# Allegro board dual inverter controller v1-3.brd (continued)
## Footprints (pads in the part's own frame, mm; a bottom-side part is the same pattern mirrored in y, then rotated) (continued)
OKI-78SR-H
  rect 1.499x1.499 hole 0.991: 1(0,2.54)
  round 1.499 hole 0.991: 2(0,0) 3(0,-2.54)
PHOENIX_1766877
  round 2.286 hole 1.397: 1(0,0) 2(0,-7.62) 3(0,-15.24) 4(0,-22.86) 5(0,-30.48) 6(0,-38.1) 7(0,-45.72) 8(0,-53.34) 9(0,-60.96) 10(0,-68.58) 11(0,-76.2) 12(0,-83.82)
POWER-SO8
  rect 0.63x0.65 smd: 1(-2.735,1.905) 2(-2.735,0.635) 3(-2.735,-0.635) 4(-2.735,-1.905) 5(2.735,-1.905) 6(2.735,-0.635) 7(2.735,0.635) 8(2.735,1.905)
RESC1608X55N
  rect 0.9x1 smd: 1(-0.8,0) 2(0.8,0)
RESC1608X65N
  rect 0.9x1 smd: 1(-0.8,0) 2(0.8,0)
RESC2012X60N
  rect 0.95x1.4 smd: 1(-1,0) 2(1,0)
RESC2012X70N
  rect 1.05x1.4 smd: 1(-0.95,0) 2(0.95,0)
RESC3216X65N
  rect 1.15x1.8 smd: 1(-1.45,0) 2(1.45,0)
RESC6432X70N
  rect 1.25x3.4 smd: 1(-3.05,0) 2(3.05,0)
RJ45_VERT_SHIELD_CON
  round 4.064 hole 3.556: (-10.16,6.35) (1.27,6.35)
  round 1.524 hole 1.016: 1(0,0) 2(-1.27,-2.54) 3(-2.54,0) 4(-3.81,-2.54) 5(-5.08,0) 6(-6.35,-2.54) 7(-7.62,0) 8(-8.89,-2.54)
  round 2.54 hole 1.702: S1(3.353,9.398) S2(-12.243,9.398)
RW-20_ADI
  rect 1.676x0.508 smd: 1(-4.636,5.715) 2(-4.636,4.445) 3(-4.636,3.175) 4(-4.636,1.905) 5(-4.636,0.635) 6(-4.636,-0.635) 7(-4.636,-1.905) 8(-4.636,-3.175) 9(-4.636,-4.445) 10(-4.636,-5.715) 11(4.636,-5.715) 12(4.636,-4.445) 13(4.636,-3.175) 14(4.636,-1.905) 15(4.636,-0.635) 16(4.636,0.635) 17(4.636,1.905) 18(4.636,3.175) 19(4.636,4.445) 20(4.636,5.715)
SOD-123F-AC
  rect 0.914x1.27 smd: 1(1.651,0) 2(-1.651,0)
SOD-323-AC
  rect 0.635x0.838 smd: A(-1.118,0) C(1.27,0)
SOP65P640X120-20AN
  rect 1.5x0.45 smd: 1(-2.95,2.925) 2(-2.95,2.275) 3(-2.95,1.625) 4(-2.95,0.975) 5(-2.95,0.325) 6(-2.95,-0.325) 7(-2.95,-0.975) 8(-2.95,-1.625) 9(-2.95,-2.275) 10(-2.95,-2.925) 11(2.95,-2.925) 12(2.95,-2.275) 13(2.95,-1.625) 14(2.95,-0.975) 15(2.95,-0.325) 16(2.95,0.325) 17(2.95,0.975) 18(2.95,1.625) 19(2.95,2.275) 20(2.95,2.925)
SOP65P640X120-24N
  rect 1.45x0.45 smd: 1(-2.95,3.575) 2(-2.95,2.925) 3(-2.95,2.275) 4(-2.95,1.625) 5(-2.95,0.975) 6(-2.95,0.325) 7(-2.95,-0.325) 8(-2.95,-0.975) 9(-2.95,-1.625) 10(-2.95,-2.275) 11(-2.95,-2.925) 12(-2.95,-3.575) 13(2.95,-3.575) 14(2.95,-2.925) 15(2.95,-2.275) 16(2.95,-1.625) 17(2.95,-0.975) 18(2.95,-0.325) 19(2.95,0.325) 20(2.95,0.975) 21(2.95,1.625) 22(2.95,2.275) 23(2.95,2.925) 24(2.95,3.575)
SOT23-5_0_95X2_70P_H1_22
  rect 1.05x0.6 smd: 1(-1.35,0.95) 2(-1.35,0) 3(-1.35,-0.95) 4(1.35,-0.95) 5(1.35,0.95)
SOT23-5_0_95X2_70P_H1_45
  rect 1.05x0.6 smd: 1(-1.35,0.95) 2(-1.35,0) 3(-1.35,-0.95) 4(1.35,-0.95) 5(1.35,0.95)
SOT363_NEX
  rect 0.787x0.356 smd: 1(-1.067,0.65) 2(-1.067,0) 3(-1.067,-0.65) 4(1.067,-0.65) 5(1.067,0) 6(1.067,0.65)
SOT-23-3-D
  rect 0.787x0.889 smd: 1(3.327,2.87) 2(1.448,2.87) 3(2.388,0.864)
SOT_23_3
  rect 0.787x0.889 smd: 1(3.327,2.87) 2(1.448,2.87) 3(2.388,0.864)
SOT_23_6
  rect 0.61x1.067 smd: 1(0,0) 2(0.953,0) 3(1.905,0) 4(1.905,2.692) 5(0.953,2.692) 6(0,2.692)
TSSOP-14
  rect 1.651x0.406 smd: 1(0,0) 2(0,-0.66) 3(0,-1.321) 4(0,-1.981) 5(0,-2.642) 6(0,-3.302) 7(0,-3.962) 8(6.096,-3.962) 9(6.096,-3.302) 10(6.096,-2.642) 11(6.096,-1.981) 12(6.096,-1.321) 13(6.096,-0.66) 14(6.096,0)
TSSOP-16P_P65MM
  oval 1.6x0.45 smd: 1(-2.85,2.275) 2(-2.85,1.625) 3(-2.85,0.975) 4(-2.85,0.325) 5(-2.85,-0.325) 6(-2.85,-0.975) 7(-2.85,-1.625) 8(-2.85,-2.275) 9(2.85,-2.275) 10(2.85,-1.625) 11(2.85,-0.975) 12(2.85,-0.325) 13(2.85,0.325) 14(2.85,0.975) 15(2.85,1.625) 16(2.85,2.275)
unnamed#2
  round 0.025 hole 3.277 unplated: (0,0)
VFSOP-8
  rect 0.762x0.254 smd: 1(-1.549,0.762) 2(-1.549,0.254) 3(-1.549,-0.254) 4(-1.549,-0.762) 5(1.549,-0.762) 6(1.549,-0.254) 7(1.549,0.254) 8(1.549,0.762)

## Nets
+1V5REF: CT58.1 RT61.1 RT73.1 RT90.1 RT112.1 RT136.1 RT173.1 UT16.1(VREF/2)
+1V5REF_RSLV: CB46.1 CT48.1 CT49.1 CT56.1 CT57.1 CT66.1 CT67.1 CT74.1 CT75.1 RT91.2 RT100.2 RT113.2 RT122.2 UB16.1(VREF/2)
+3V3: CB5.1 CB8.1 CB12.1 CB13.1 CB14.1 CB21.1 CB22.1 CB23.1 CB27.1 CB28.1 CB29.1 CB36.1 CB37.1 CB38.1 CB39.1 CB43.1 CB54.1 CB68.1 CB70.1 CB72.1 CT2.1 CT7.1 CT16.1 CT21.1 CT31.1 CT33.1 CT36.1 CT42.1 CT43.1 CT51.1 CT52.1 CT60.1 CT62.1 CT69.1 CT70.1 CT89.1 CT108.1 CT119.1 CT125.1 CT126.1 CT130.1 CT145.1 CT156.1 CT160.1 CT163.1 JT2.7 JT17.5 RB2.1 RB3.1 RB6.1 RB13.1 RB27.2 RB29.1 RB30.1 RB31.1 RB47.1 RB48.1 RB49.1 RB91.1 RB95.1 RB110.1 RB111.1 RB113.1 RB118.1 RT53.2 RT54.2 RT78.1 RT192.1 RT229.2 RT238.2 UB1.3 UB1.4 UB2.5 UB3.3 UB3.8(VCC) UB4.3 UB4.8(VCC) UB5.3 UB5.8(VCC) UB6.5 UB7.5 UB8.5 UB9.3 UB9.8(VCC) UB10.3 UB10.8(VCC) UB11.3 UB11.8(VCC) UB12.5 UB13.5 UB14.5 UB15.5 UB16.3 UB16.4 UB17.5 UB20.5 UB21.3 UB21.4 UB22.1 UT1.16 UT2.16 UT3.5 UT4.16 UT8.16 UT10.5 UT11.5 UT13.5 UT14.5 UT15.5 UT16.3 UT16.4 UT17.5 UT18.5 UT19.5 UT21.5 UT25.16 UT26.16 UT32.5 UT33.3(OUTPUT) UT34.16 UT35.16 UT38.4 UT39.5 UT40.5
+3VREF_A: CB4.1 RB15.1 RB16.1 RB17.1 UB1.5
+3VREF_B: CB71.1 RB92.1 RB93.1 RB94.1 UB21.5
+5V: CB44.1 CB45.1 CB73.1 CT22.1 CT23.1 CT24.1 CT121.1 CT122.1 CT123.1 CT128.1 CT129.1 CT146.1 CT150.1 CT153.1 JB1.2 JB5.2 JT26.48 JT26.84 JT26.98 JT26.112 JT26.158 JT26.180 JT41.4 JT41.9(PIN9) RT148.1 RT156.1 RT166.1 RT172.1 RT186.1 RT193.1 RT194.1 UB18.20 UB19.20 UB22.23(VCCB1) UB22.24 UT5.4 UT6.4 UT7.4 UT27.20 UT28.20 UT29.4 UT30.4 UT31.4 UT36.3(OUTPUT) UT38.3
+5V-ISO: CT151.1 CT154.1 CT155.1 JT3.9 LT26.2 UT38.16
+12V: CT90.1 CT111.1 CT134.1 CT147.1 DT2.A JB2.1 JB3.1 JB4.1 JB6.1 JB7.1 JB8.1 JT2.1 LT13.1 RT145.1 RT146.2 RT220.2 UT22.5 UT33.1 UT36.1 UT37.8(VOUT)
+15V: CT87.1 CT95.1 CT161.1 DT10.2 DT10.5 DT11.2 DT11.5 DT12.2 DT12.5 DT13.2 DT13.5 DT14.2 DT14.5 DT15.2 DT15.5 QT1.5 QT1.6 QT1.7 QT1.8 RB114.1 RB117.1 RT235.1 RT239.1 UT41.10(VS_O(2)) UT41.11 UT41.12 UT43.10(VS_O(2)) UT43.11 UT43.12
VIN: JT42.1 QT3.5 QT3.6 QT3.7 QT3.8 RT217.1 RT223.1 UT37.1
0: CB1.1 CB2.1 CB3.1 CB4.2 CB5.2 CB6.2 CB8.2 CB9.1 CB10.1 CB11.2 CB12.2 CB13.2 CB14.2 CB18.1 CB19.1 CB20.1 CB21.2 CB22.2 CB23.2 CB27.2 CB28.2 CB29.2 CB33.1 CB34.1 CB35.1 CB36.2 CB37.2 CB38.2 CB39.2 CB43.2 CB44.2 CB45.2 CB46.2 CB47.2 CB48.2 CB49.2 CB50.2 CB51.2 CB52.2 CB53.2 CB54.2 CB55.2 CB56.2 CB57.2 CB58.2 CB59.2 CB60.2 CB61.2 CB62.2 CB63.2 CB64.2 CB65.2 CB66.2 CB67.2 CB68.2 CB69.2 CB70.2 CB71.2 CB72.2 CB73.2 CB74.1 CB75.1 CB76.1 CB79.2 CB81.2 CB83.2 CB84.2 CT1.2 CT2.2 CT3.2 CT4.2 CT5.2 CT6.2 CT7.2 CT8.2 CT9.1 CT10.2 CT11.1 CT12.2 CT13.1 CT14.2 CT15.1 CT16.2 CT21.2 CT22.2 CT23.2 CT24.2 CT31.2 CT33.2 CT34.1 CT36.2 CT37.2 CT39.1 CT40.2 CT42.2 CT43.2 CT45.2 CT47.1 CT48.2 CT51.2 CT52.2 CT54.2 CT56.2 CT58.2 CT59.2 CT60.2 CT62.2 CT63.2 CT65.1 CT66.2 CT69.2 CT70.2 CT72.2 CT74.2 CT81.1 CT87.2 CT88.2 CT89.2 CT90.2 CT91.2 CT95.2 CT97.1 CT98.1 CT99.2 CT100.2 CT103.1 CT104.2 CT106.2 CT107.2 CT108.2 CT109.2 CT110.2 CT111.2 CT112.1 CT116.2 CT118.2 CT119.2 CT120.2 CT121.2 CT122.2 CT123.2 CT124.2 CT125.2 CT126.2 CT127.2 CT128.2 CT129.2 CT130.2 CT131.2 CT134.2 CT136.1 CT137.2 CT138.1 CT139.2 CT140.1 CT141.2 CT145.2 CT146.2 CT147.2 CT148.2 CT149.2 CT150.2 CT153.2 CT156.2 CT160.2 CT161.2 CT163.2 CT164.1 DT4.2(C) DT5.2(C) DT6.2(C) DT7.2(C) DT8.2(C) DT10.1 DT10.4(C2) DT11.1 DT11.4(C2) DT12.1 DT12.4(C2) DT13.1 DT13.4(C2) DT14.1 DT14.4(C2) DT15.1 DT15.4(C2) JB1.1 JB1.S1 JB1.S2(SHIELD2) JB2.2 JB2.12 JB2.14 JB2.16 JB3.2 JB3.12 JB3.14 JB3.16 JB4.2 JB4.12 JB4.14 JB4.16 JB5.1 JB5.S1 JB5.S2(SHIELD2) JB6.2 JB6.12 JB6.14 JB6.16 JB7.2 JB7.12 JB7.14 JB7.16 JB8.2 JB8.12 JB8.14 JB8.16 JT2.2 JT2.8 JT4.2 JT4.3 JT4.4 JT4.5 JT5.2 JT5.3 JT5.4 JT5.5 JT6.2 JT6.3 JT6.4 JT6.5 JT7.2 JT7.3 JT7.4 JT7.5 JT8.2 JT8.3 JT8.4 JT8.5 JT9.2 JT9.3 JT9.4 JT9.5 JT10.2 JT10.3 JT10.4 JT10.5 JT11.2 JT11.3 JT11.4 JT11.5 JT12.2 JT12.3 JT12.4 JT12.5 JT13.2 JT13.3 JT13.4 JT13.5 JT14.2 JT14.3 JT14.4 JT14.5 JT15.2 JT16.2 JT16.3 JT16.4 JT16.5 JT17.4 JT17.8 JT17.10 JT17.12 JT19.2 JT19.3 JT19.4 JT19.5 JT20.2 JT20.3 JT20.4 JT20.5 JT21.2 JT21.3 JT21.4 JT21.5 JT23.2 JT23.3 JT23.4 JT23.5 JT24.2 JT24.3 JT24.4 JT24.5 JT25.2 JT25.3 JT25.4 JT25.5 JT26.7 JT26.10 JT26.13 JT26.16 JT26.19 JT26.22 JT26.29 JT26.35 JT26.38 JT26.46 JT26.47 JT26.65 JT26.83 JT26.97 JT26.111 JT26.135 JT26.157 JT26.179 JT26.G1 JT26.G2 JT26.G3 JT26.G4 JT27.2 JT27.3 JT27.4 JT27.5 JT28.2 JT28.3 JT28.4 JT28.5 JT29.2 JT29.3 JT29.4 JT29.5 JT30.2 JT30.3 JT30.4 JT30.5 JT31.2 JT31.3 JT31.4 JT31.5 JT32.2 JT32.3 JT32.4 JT32.5 JT33.2 JT33.3 JT33.4 JT33.5 JT34.2 JT34.3 JT34.4 JT34.5 JT35.2 JT35.3 JT35.4 JT35.5 JT36.2 JT36.3 JT36.4 JT36.5 JT37.2 JT37.3 JT37.4 JT37.5 JT38.2 JT38.3 JT38.4 JT38.5 JT39.2 JT39.3 JT39.4 JT39.5 JT40.2 JT40.3 JT40.4 JT40.5 JT41.5 JT41.10 JT42.2 JT42.3 RB1.1 RB4.1 RB5.2 RB7.2 RB9.2 RB11.2 RB14.2 RB28.1 RB90.1 RB96.1 RB98.2 RB100.2 RB102.2 RB109.2 RB112.2 RB115.2 RB116.2 RB119.2 RB120.2 RT27.1 RT144.1 RT147.2 RT160.2 RT221.2 RT225.2 RT226.2 RT227.2 RT234.2 RT245.2 UB1.2 UB2.2(V-) UB3.1 UB3.4 UB4.1 UB4.4 UB5.1 UB5.4 UB6.2(V-) UB7.2(V-) UB8.2(V-) UB9.1 UB9.4 UB10.1 UB10.4 UB11.1 UB11.4 UB12.2(V-) UB13.2(V-) UB14.2(V-) UB15.2 UB16.2 UB17.2 UB18.1 UB18.2 UB18.3 UB18.10 UB18.19 UB19.1 UB19.5 UB19.6 UB19.7 UB19.8 UB19.9 UB19.10 UB19.19 UB20.2 UB21.2 UB22.2 UB22.11 UB22.12 UB22.13 UB22.14 UB22.15 UB22.22 UT1.8 UT2.8 UT3.2(V-) UT4.8 UT5.2 UT5.3 UT5.11 UT6.2 UT6.3 UT6.11 UT7.2 UT7.3 UT7.11 UT8.8 UT10.2(V-) UT11.2(V-) UT13.2(V-) UT14.2(V-) UT15.2(V-) UT16.2 UT17.2(V-) UT18.2(V-) UT19.2(V-) UT21.2(V-) UT22.16 UT22.17 UT24.2(S) UT25.8 UT26.8 UT27.1 UT27.2 UT27.3 UT27.10 UT27.19 UT28.1 UT28.5 UT28.6 UT28.7 UT28.8 UT28.9 UT28.10 UT28.19 UT29.2 UT29.3 UT29.11 UT30.2 UT30.3 UT30.11 UT31.2 UT31.3 UT31.11 UT32.2(V-) UT33.2 UT34.8 UT35.8 UT36.2 UT37.5 UT38.1 UT38.2 UT38.10 UT39.2(V-) UT40.2(V-) UT41.6 UT41.14 UT41.EPAD UT43.6 UT43.14 UT43.EPAD
1: CT151.2 CT154.2 CT155.2 DT9.3(A3) JT3.3 JT3.5 JT3.10 JT3.11(SHIELD1) LT27.2 RT228.2 UT38.11 UT38.15
CANA-H: DT9.1 JT3.7 RT224.1 UT38.14
CANA-L: DT9.2 JT3.2 RT224.2 UT38.13
CANA-RX: JT26.80 UT38.5
CANA-TX: JT26.82 UT38.7
CASE-TEMP: CB11.1 JT26.30 RB26.2
COS-A: CT54.1 JT20.1(SIGNAL) JT26.36 RT99.2
COS-A-N: CT53.1 DT13.3 JT18.6 RT95.1 RT96.1
COS-A-P: CT53.2 DT13.6 JT18.5 RT93.1 RT95.2
COS-B: CT72.1 JT26.42 JT27.1(SIGNAL) RT121.2
COS-B-N: CT71.1 DT10.3 JT22.6 RT117.1 RT119.1
COS-B-P: CT71.2 DT10.6 JT22.5 RT115.1 RT117.2
CURRENT-U: CB55.1 JT11.1(SIGNAL) JT26.12 RT50.2
CURRENT-U_N: JB1.3 RT4.2 RT14.1
CURRENT-U_P: JB1.6 RT4.1 RT15.1
CURRENT-V: CB56.1 JT4.1(SIGNAL) JT26.14 RT51.2
CURRENT-V_N: JB1.5 RT5.2 RT16.1
CURRENT-V_P: JB1.4 RT5.1 RT17.1
CURRENT-W: CB57.1 JT12.1(SIGNAL) JT26.18 RT52.2
CURRENT-W_N: JB1.7 RT6.2 RT18.1
CURRENT-W_P: JB1.8 RT6.1 RT19.1
CURRENT-X: CB60.1 JT26.26 JT40.1(SIGNAL) RT171.2
CURRENT-X_N: JB5.7 RT210.1 RT213.2
CURRENT-X_P: JB5.8 RT209.1 RT213.1
CURRENT-Y: CB59.1 JT26.24 JT39.1(SIGNAL) RT170.2
CURRENT-Y_N: JB5.5 RT208.1 RT212.2
CURRENT-Y_P: JB5.4 RT207.1 RT212.1
CURRENT-Z: CB58.1 JT26.20 JT38.1(SIGNAL) RT169.2
CURRENT-Z_N: JB5.3 RT206.1 RT211.2
CURRENT-Z_P: JB5.6 RT205.1 RT211.1
EMUI: JT17.14 JT26.1
EMUO: JT17.13 JT26.2
EXC-A-N: CT158.2 DT15.3 JT18.2 RT233.2 UT41.9
EXC-A-P: CT157.2 DT15.6 JT18.1 RT230.2 UT41.13
EXC-B-N: CT166.2 DT12.3 JT22.2 RT244.2 UT43.9
EXC-B-P: CT162.2 DT12.6 JT22.1 RT237.2 UT43.13
GLOBAL-FAULT-ALL: JT16.1(SIGNAL) JT26.134 UB17.4(Y)
GLOBAL-FAULT-UVW: JT26.130 UB15.4(Y) UB17.3
GLOBAL-FAULT-XYZ: JT26.132 UB17.6 UB20.4(Y)
I2CA-SCL: JT2.9 JT26.87 RT54.1
I2CA-SDA: JT2.10 JT26.85 RT53.1
LED-G: JT26.133 RT154.1
LED-R: JT26.129 RT152.1
LED-Y: JT26.131 RT153.1
PWM7A: JT2.12 JT26.58
PWM7B: JT2.11 JT26.60
PWM8A: JT2.14 JT26.62
PWM8B: JT2.13 JT26.64
PWM9A: JT26.167 RT66.1
PWM9B: JT26.168 RT75.1
QEA_A: JT26.68 UB22.3
QEA_B: JT26.70 UB22.4
QEA_I: JT26.74 UB22.5
QEB_A: JT26.100 UB22.6
QEB_B: JT26.102 UB22.7
QEB_I: JT26.106 UB22.8
QEPA-A-IN: CT118.1 JT41.1 RT186.2 UB22.21
QEPA-B-IN: CT131.1 JT41.2 RT194.2 UB22.20
QEPA-I-IN: CT116.1 JT41.3 RT172.2 UB22.19
QEPB-A-IN: CT106.1 JT41.6 RT166.2 UB22.18
QEPB-B-IN: CT99.1 JT41.7 RT156.2 UB22.17
QEPB-I-IN: CT91.1 JT41.8 RT148.2 UB22.16
RSLV-A-PWM: JT26.169 RT163.1
RSLV-B-PWM: JT26.170 RT242.1
SD-C1: JT2.15 JT26.101
SD-C2: JT2.17 JT26.105
SD-C3: JT2.19 JT26.109
SD-D1: JT2.16 JT26.99
SD-D2: JT2.18 JT26.103
SD-D3: JT2.20 JT26.107
SHUTDOWN+15V: JT26.155 RT160.1 RT161.1
SIN-A: CT45.1 JT19.1(SIGNAL) JT26.34 RT83.2
SIN-A-N: CT44.1 DT14.3 JT18.4 RT80.1 RT81.1
SIN-A-P: CT44.2 DT14.6 JT18.3 RT79.1 RT80.2
SIN-B: CT63.1 JT23.1(SIGNAL) JT26.40 RT105.2
SIN-B-N: CT61.1 DT11.3 JT22.4 RT102.1 RT103.1
SIN-B-P: CT61.2 DT11.6 JT22.3 RT101.1 RT102.2
SPIA-CLK: JT2.6 JT26.71
SPIA-MISO: JT2.5 JT26.69
SPIA-MOSI: JT2.3 JT26.67
SPIA-STE: JT2.4 JT26.73
TCK: JT17.9 JT17.11 JT26.5
TDI: JT17.3 JT26.8
TDO: JT17.7 JT26.6
TMS: JT17.1 JT26.3
TRST: JT17.2 JT26.4
U-FAULT: JT26.122 UB15.1 UT8.3
U-FAULT-N: JB4.8 LT12.1
U-FAULT-N-FILTER: CT27.2 LT12.2 RT49.2 UT8.1
U-FAULT-P: JB4.7 LT9.1
U-FAULT-P-FILTER: CT27.1 LT9.2 RT49.1 UT8.2
U-LEN: JB4.13 UB18.12
U-LEN-OUT: JT26.144 UB18.8
U-OCEN: JB4.15 UB18.11(Y8)
U-OCEN-OUT: JT26.142 UB18.9
U-PSDIS: JB4.11 UB18.13
U-PSDIS-OUT: JT26.146 UB18.7
U-RTD: JT26.92 RB32.1 UB3.2 UT8.5
U-RTD-N: JB4.10 LT3.1
U-RTD-N-FILTER: CT20.2 LT3.2 RT32.2 UT8.7
U-RTD-P: JB4.9 LT6.1
U-RTD-P-FILTER: CT20.1 LT6.2 RT32.1 UT8.6
U-TEMP: CB48.1 JT26.25 RB66.2
UHS-PWM: JT9.1(SIGNAL) JT26.49 RT20.1
UHS-PWM-N: JB4.4 UT1.3
UHS-PWM-P: JB4.3 UT1.2
ULS-PWM: JT10.1(SIGNAL) JT26.51 RT3.1
ULS-PWM-N: JB4.6 UT1.5
ULS-PWM-P: JB4.5 UT1.6
V-FAULT: JT26.124 UB15.3 UT8.11
V-FAULT-N: JB3.8 LT1.1
V-FAULT-N-FILTER: CT18.2 LT1.2 RT30.2 UT8.9
V-FAULT-P: JB3.7 LT4.1
V-FAULT-P-FILTER: CT18.1 LT4.2 RT30.1 UT8.10
V-LEN: JB3.13 UB18.15
V-LEN-OUT: JT26.152 UB18.5
V-OCEN: JB3.15 UB18.14
V-OCEN-OUT: JT26.150 UB18.6
V-PSDIS: JB3.11 UB18.16
V-PSDIS-OUT: JT26.154 UB18.4
V-RTD: JT26.94 RB33.1 UB4.2 UT8.13(Y4)
V-RTD-N: JB3.10 LT11.1
V-RTD-N-FILTER: CT26.2 LT11.2 RT48.2 UT8.15
V-RTD-P: JB3.9 LT8.1
V-RTD-P-FILTER: CT26.1 LT8.2 RT48.1 UT8.14
V-TEMP: CB49.1 JT26.27 RB67.2
V_U+: JT43.12 RT55.1
V_U-: JT43.11 RB19.1
V_V+: JT43.10 RT67.1
V_V-: JT43.9 RB41.1
V_W+: JT43.8 RT84.1
V_W-: JT43.7 RB59.1
V_X+: JT43.6 RT106.1
V_X-: JT43.5 RB74.1
V_Y+: JT43.4 RT130.1
V_Y-: JT43.3 RB83.1
V_Z+: JT43.2 RT174.1
V_Z-: JT43.1 RB103.1
VDC-M: JT1.2 RT37.1
VDC-P: JT1.1 RT7.1
VHS-PWM: JT7.1(SIGNAL) JT26.53 RT2.1
VHS-PWM-N: JB3.4 UT1.11
VHS-PWM-P: JB3.3 UT1.10
VLS-PWM: JT8.1(SIGNAL) JT26.55 RT13.1
VLS-PWM-N: JB3.6 UT1.13(Z4)
VLS-PWM-P: JB3.5 UT1.14
VSENSE-DC: CB61.1 JT21.1(SIGNAL) JT26.28 RB65.2
VSENSE-U: CB62.1 JT24.1(SIGNAL) JT26.9 RB72.2
VSENSE-V: CB63.1 JT25.1(SIGNAL) JT26.11 RB73.2
VSENSE-W: CB64.1 JT26.15 JT28.1(SIGNAL) RB80.2
VSENSE-X: CB65.1 JT26.17 JT29.1(SIGNAL) RB81.2
VSENSE-Y: CB66.1 JT26.21 JT30.1(SIGNAL) RB82.2
VSENSE-Z: CB67.1 JT26.23 JT31.1(SIGNAL) RB89.2
W-FAULT: JT26.126 UB15.6 UT4.3
W-FAULT-N: JB2.8 LT2.1
W-FAULT-N-FILTER: CT19.2 LT2.2 RT31.2 UT4.1
W-FAULT-P: JB2.7 LT5.1
W-FAULT-P-FILTER: CT19.1 LT5.2 RT31.1 UT4.2
W-LEN: JB2.13 UB19.17
W-LEN-OUT: JT26.162 UB19.3
W-OCEN: JB2.15 UB19.16
W-OCEN-OUT: JT26.160 UB19.4
W-PSDIS: JB2.11 UB19.18
W-PSDIS-OUT: JT26.164 UB19.2
W-RTD: JT26.96 RB34.1 UB5.2 UT4.5
W-RTD-N: JB2.10 LT10.1
W-RTD-N-FILTER: CT25.2 LT10.2 RT47.2 UT4.7
W-RTD-P: JB2.9 LT7.1
W-RTD-P-FILTER: CT25.1 LT7.2 RT47.1 UT4.6
W-TEMP: CB50.1 JT26.31 RB68.2
WHS-PWM: JT5.1(SIGNAL) JT26.50 RT1.1
WHS-PWM-N: JB2.4 UT2.3
WHS-PWM-P: JB2.3 UT2.2
WLS-PWM: JT6.1(SIGNAL) JT26.52 RT28.1
WLS-PWM-N: JB2.6 UT2.5
WLS-PWM-P: JB2.5 UT2.6
X-FAULT: JT26.121 UB20.1 UT35.3
X-FAULT-N: JB8.8 LT25.1
X-FAULT-N-FILTER: CT144.2 LT25.2 RT216.2 UT35.1
X-FAULT-P: JB8.7 LT22.1
X-FAULT-P-FILTER: CT144.1 LT22.2 RT216.1 UT35.2
X-LEN: JB8.13 UT27.12
X-LEN-OUT: JT26.143 UT27.8
X-OCEN: JB8.15 UT27.11(Y8)
X-OCEN-OUT: JT26.141 UT27.9
X-PSDIS: JB8.11 UT27.13
X-PSDIS-OUT: JT26.145 UT27.7
X-RTD: JT26.89 RB50.1 UB9.2 UT35.5
X-RTD-N: JB8.10 LT16.1
X-RTD-N-FILTER: CT135.2 LT16.2 RT204.2 UT35.7
X-RTD-P: JB8.9 LT19.1
X-RTD-P-FILTER: CT135.1 LT19.2 RT204.1 UT35.6
X-TEMP: CB51.1 JT26.33 RB69.2
XHS-PWM: JT26.54 JT36.1(SIGNAL) RT190.1
XHS-PWM-N: JB8.4 UT25.3
XHS-PWM-P: JB8.3 UT25.2
XLS-PWM: JT26.56 JT37.1(SIGNAL) RT168.1
XLS-PWM-N: JB8.6 UT25.5
XLS-PWM-P: JB8.5 UT25.6
Y-FAULT: JT26.123 UB20.3 UT35.11
Y-FAULT-N: JB7.8 LT14.1
Y-FAULT-N-FILTER: CT132.2 LT14.2 RT196.2 UT35.9
Y-FAULT-P: JB7.7 LT17.1
Y-FAULT-P-FILTER: CT132.1 LT17.2 RT196.1 UT35.10
Y-LEN: JB7.13 UT27.15
Y-LEN-OUT: JT26.151 UT27.5
Y-OCEN: JB7.15 UT27.14
Y-OCEN-OUT: JT26.149 UT27.6
Y-PSDIS: JB7.11 UT27.16
Y-PSDIS-OUT: JT26.153 UT27.4
Y-RTD: JT26.91 RB51.1 UB10.2 UT35.13(Y4)
Y-RTD-N: JB7.10 LT24.1
Y-RTD-N-FILTER: CT143.2 LT24.2 RT215.2 UT35.15
Y-RTD-P: JB7.9 LT21.1
Y-RTD-P-FILTER: CT143.1 LT21.2 RT215.1 UT35.14
Y-TEMP: CB52.1 JT26.37 RB70.2
YHS-PWM: JT26.57 JT34.1(SIGNAL) RT167.1
YHS-PWM-N: JB7.4 UT25.11
YHS-PWM-P: JB7.3 UT25.10
YLS-PWM: JT26.59 JT35.1(SIGNAL) RT185.1
YLS-PWM-N: JB7.6 UT25.13(Z4)
YLS-PWM-P: JB7.5 UT25.14
Z-FAULT: JT26.125 UB20.6 UT34.3
Z-FAULT-N: JB6.8 LT15.1
Z-FAULT-N-FILTER: CT133.2 LT15.2 RT197.2 UT34.1
Z-FAULT-P: JB6.7 LT18.1
Z-FAULT-P-FILTER: CT133.1 LT18.2 RT197.1 UT34.2
Z-LEN: JB6.13 UT28.17
Z-LEN-OUT: JT26.161 UT28.3
Z-OCEN: JB6.15 UT28.16
Z-OCEN-OUT: JT26.159 UT28.4
Z-PSDIS: JB6.11 UT28.18
Z-PSDIS-OUT: JT26.163 UT28.2
Z-RTD: JT26.93 RB52.1 UB11.2 UT34.5
Z-RTD-N: JB6.10 LT23.1
Z-RTD-N-FILTER: CT142.2 LT23.2 RT214.2 UT34.7
Z-RTD-P: JB6.9 LT20.1
Z-RTD-P-FILTER: CT142.1 LT20.2 RT214.1 UT34.6
Z-TEMP: CB53.1 JT26.39 RB71.2
ZHS-PWM: JT26.61 JT32.1(SIGNAL) RT165.1
ZHS-PWM-N: JB6.4 UT26.3
ZHS-PWM-P: JB6.3 UT26.2
ZLS-PWM: JT26.63 JT33.1(SIGNAL) RT195.1
ZLS-PWM-N: JB6.6 UT26.5
ZLS-PWM-P: JB6.5 UT26.6
N07282: RB13.2 UT8.4
N07299: RB5.1 UT8.12
N07508: RB6.2 UT4.4
N07516: RB14.1 UT4.12
N07693: RB3.2 UT1.4
N07878: RB2.2 UT2.4
N09835: CT6.1 RT20.2 UT1.1
N10049: CT4.1 RT3.2 UT1.7
N10085: CT3.1 RT2.2 UT1.9
N10121: CT5.1 RT13.2 UT1.15
N11382: RB1.2 UT1.12
N11987: RB4.2 UT2.12
N12714: CT1.1 RT1.2 UT2.1
N12754: CT14.1 RT28.2 UT2.7
N16187: CB24.2 RB66.1 UB6.1 UB6.4
N16636: CB24.1 RB35.2 RB38.1
N16643: CB18.2 RB38.2 UB6.3
N18013: CB25.1 RB36.2 RB39.1
N18021: CB25.2 RB67.1 UB7.1 UB7.4
N18093: CB19.2 RB39.2 UB7.3
N18488: CB26.1 RB37.2 RB40.1
N18496: CB26.2 RB68.1 UB8.1 UB8.4
N18568: CB20.2 RB40.2 UB8.3
N76078: CT15.2 RT12.2 RT27.2 RT29.1
N76134: RT29.2 UT3.3
N76224: CT17.2 RB65.1 RT36.2 UT3.1
N76236: RT43.2 UT3.4
N76260: CT17.1 RT36.1 RT42.2 RT43.1
N78650: CB7.1 RB18.1 RB25.2
N78658: CB7.2 RB26.1 UB2.1 UB2.4
N78724: CB9.2 RB18.2 UB2.3
N79088: CB10.2 RB25.1 RB27.1 RB28.2
N88263: DT7.1 RT192.2
N88433: DT8.1 RT193.2
N93191: DT4.1 RT152.2
N93195: DT6.1 RT154.2
N93199: DT5.1 RT153.2
N139937: RT10.2 RT11.1
N139941: RT11.2 RT12.1
N140053: RT40.2 RT41.1
N140057: RT41.2 RT42.1
N147166: QT2.1 QT2.2 QT2.3(S2) QT3.1 QT3.2 QT3.3(S2)
N148075: QT2.4 QT3.4 RT222.2 UT37.10
N148197: CT149.1 RT222.1
N148540: QT2.5 QT2.6 QT2.7 QT2.8 RT220.1 UT37.9
N149103: RT217.2 RT218.1 UT37.6
N149107: RT218.2 RT219.1 UT37.2
N149113: RT219.2 RT221.1 UT37.3
N149983: CT148.1 UT37.4
N150621: RT223.2 UT37.7
N273504: RB32.2 RB35.1 UB3.5
N273798: CB15.2 UB3.6
N273802: CB15.1 RB29.2 UB3.7
N275299: RB33.2 RB36.1 UB4.5
N275399: CB16.1 RB30.2 UB4.7
N275407: CB16.2 UB4.6
N275841: RB34.2 RB37.1 UB5.5
N275941: CB17.1 RB31.2 UB5.7
N275949: CB17.2 UB5.6
N353091: RB111.2 UT35.4
N353097: RB109.1 UT35.12
N353101: RB110.2 UT34.4
N353105: RB112.1 UT34.12
N353111: RB95.2 UT25.4
N353117: RB91.2 UT26.4
N353179: CT124.1 RT190.2 UT25.1
N353185: CT110.1 RT168.2 UT25.7
N353187: CT109.1 RT167.2 UT25.9
N353189: CT120.1 RT185.2 UT25.15
N353203: RB90.2 UT25.12
N353215: RB96.2 UT26.12
N353221: CT107.1 RT165.2 UT26.1
N353229: CT127.1 RT195.2 UT26.7
N368949: RB50.2 RB53.1 UB9.5
N368957: CB40.1 RB53.2 RB56.1
N368965: CB40.2 RB69.1 UB12.1 UB12.4
N369195: CB33.2 RB56.2 UB12.3
N369283: CB30.1 RB47.2 UB9.7
N369291: CB30.2 UB9.6
N369511: CB41.1 RB54.2 RB57.1
N369519: CB41.2 RB70.1 UB13.1 UB13.4
N369535: RB51.2 RB54.1 UB10.5
N369765: CB34.2 RB57.2 UB13.3
N369853: CB31.1 RB48.2 UB10.7
N369861: CB31.2 UB10.6
N370089: RB52.2 RB55.1 UB11.5
N370097: CB42.1 RB55.2 RB58.1
N370105: CB42.2 RB71.1 UB14.1 UB14.4
N370335: CB35.2 RB58.2 UB14.3
N370423: CB32.1 RB49.2 UB11.7
N370431: CB32.2 UB11.6
N4877770: CT8.1 RT14.2 RT21.1
N4877774: CT9.2 RT15.2 RT22.1
N4883221: RT22.2 UT5.5
N4883225: RB8.1 UT5.6 UT5.7
N4883237: RT21.2 UT5.10
N4883249: RT33.1 UT5.8 UT5.9
N4883601: CT28.1 RT33.2 RT44.1 UT5.13
N4883608: CT28.2 RT44.2 RT50.1 UT5.14(OUT4)
N4883677: CB1.2 RB7.1 RB8.2 RB15.2 UT5.12
N4893553: CB2.2 RB9.1 RB10.2 RB16.2 UT6.12
N4893669: CT11.2 RT17.2 RT24.1
N4893747: RT24.2 UT6.5
N4893767: RB10.1 UT6.6 UT6.7
N4893837: CT29.2 RT45.2 RT51.1 UT6.14(OUT4)
N4893845: CT29.1 RT34.2 RT45.1 UT6.13
N4893923: CT10.1 RT16.2 RT23.1
N4893935: RT23.2 UT6.10
N4893955: RT34.1 UT6.8 UT6.9
N4894909: CB3.2 RB11.1 RB12.2 RB17.2 UT7.12
N4895025: CT13.2 RT19.2 RT26.1
N4895103: RT26.2 UT7.5
N4895123: RB12.1 UT7.6 UT7.7
N4895193: CT30.2 RT46.2 RT52.1 UT7.14(OUT4)
N4895201: CT30.1 RT35.2 RT46.1 UT7.13
N4895279: CT12.1 RT18.2 RT25.1
N4895291: RT25.2 UT7.10
N4895311: RT35.1 UT7.8 UT7.9
N4895784: CT137.1 RT199.1 RT206.2
N4895786: CT136.2 RT198.1 RT205.2
N4895800: RT198.2 UT29.5
N4895802: RB97.1 UT29.6 UT29.7
N4895808: RT199.2 UT29.10
N4895810: RT187.1 UT29.8 UT29.9
N4895816: CT113.1 RT181.1 RT187.2 UT29.13
N4895820: CT113.2 RT169.1 RT181.2 UT29.14(OUT4)
N4895842: CB74.2 RB92.2 RB97.2 RB98.1 UT29.12
N4895902: CB75.2 RB93.2 RB99.2 RB100.1 UT30.12
N4895932: CT138.2 RT200.1 RT207.2
N4895942: RT200.2 UT30.5
N4895944: RB99.1 UT30.6 UT30.7
N4895958: CT114.2 RT170.1 RT182.2 UT30.14(OUT4)
N4895962: CT114.1 RT182.1 RT188.2 UT30.13
N4895972: CT139.1 RT201.1 RT208.2
N4895978: RT201.2 UT30.10
N4895980: RT188.1 UT30.8 UT30.9
N4896016: CB76.2 RB94.2 RB101.2 RB102.1 UT31.12
N4896046: CT140.2 RT202.1 RT209.2
N4896056: RT202.2 UT31.5
N4896058: RB101.1 UT31.6 UT31.7
N4896072: CT115.2 RT171.1 RT183.2 UT31.14(OUT4)
N4896076: CT115.1 RT183.1 RT189.2 UT31.13
N4896086: CT141.1 RT203.1 RT210.2
N4896092: RT203.2 UT31.10
N4896094: RT189.1 UT31.8 UT31.9
N4909322: JT15.1 RT78.2 UB17.1
N4927414: RB21.2 RB22.1
N4927416: RB22.2 RB23.1
N4927418: RB23.2 RB24.1
N4927420: RT57.2 RT58.1
N4927422: RT58.2 RT59.1
N4927424: RT59.2 RT60.1
N4927426: CT34.2 RT60.2 RT61.2 RT62.1
N4927452: RT69.2 RT70.1
N4927454: RT70.2 RT71.1
N4927456: RT71.2 RT72.1
N4927458: CT39.2 RT72.2 RT73.2 RT74.1
N4927466: RB43.2 RB44.1
N4927468: RB44.2 RB45.1
N4927470: RB45.2 RB46.1
N4927472: CT41.1 RB46.2 RT76.1 RT77.1
N4927476: RT86.2 RT87.1
N4927478: RT87.2 RT88.1
N4927480: RT88.2 RT89.1
N4927482: CT47.2 RT89.2 RT90.2 RT92.1
N4927490: RB61.2 RB62.1
N4927492: RB62.2 RB63.1
N4927494: RB63.2 RB64.1
N4927496: CT50.1 RB64.2 RT94.1 RT97.1
N4927508: RT55.2 RT56.1
N4927510: RB19.2 RB20.1
N4927512: RT56.2 RT57.1
N4927514: RB20.2 RB21.1
N4927522: RT67.2 RT68.1
N4927524: RT68.2 RT69.1
N4927528: RB41.2 RB42.1
N4927530: RB42.2 RB43.1
N4927534: RT84.2 RT85.1
N4927536: RT85.2 RT86.1
N4927540: RB59.2 RB60.1
N4927542: RB60.2 RB61.1
N4927556: CT35.2 RB72.1 RT64.2 UT10.1
N4927564: CT35.1 RB24.2 RT64.1 RT65.1
N4927568: RT65.2 UT10.4
N4927572: RT62.2 UT10.3
N4927618: RT74.2 UT11.3
N4927622: CT41.2 RB73.1 RT76.2 UT11.1
N4927628: RT77.2 UT11.4
N4927670: RT92.2 UT14.3
N4927674: CT50.2 RB80.1 RT94.2 UT14.1
N4927680: RT97.2 UT14.4
N4932848: RB76.2 RB77.1
N4932850: RB77.2 RB78.1
N4932852: RB78.2 RB79.1
N4932854: RT108.2 RT109.1
N4932856: RT109.2 RT110.1
N4932858: RT110.2 RT111.1
N4932860: CT65.2 RT111.2 RT112.2 RT114.1
N4932886: RT132.2 RT133.1
N4932888: RT133.2 RT134.1
N4932890: RT134.2 RT135.1
N4932892: CT81.2 RT135.2 RT136.2 RT137.1
N4932900: RB85.2 RB86.1
N4932902: RB86.2 RB87.1
N4932904: RB87.2 RB88.1
N4932906: CT86.1 RB88.2 RT141.1 RT142.1
N4932910: RT176.2 RT177.1
N4932912: RT177.2 RT178.1
N4932914: RT178.2 RT179.1
N4932916: CT112.2 RT173.2 RT179.2 RT180.1
N4932924: RB105.2 RB106.1
N4932926: RB106.2 RB107.1
N4932928: RB107.2 RB108.1
N4932930: CT117.1 RB108.2 RT184.1 RT191.1
N4932934: RT106.2 RT107.1
N4932936: RB74.2 RB75.1
N4932938: RT107.2 RT108.1
N4932940: RB75.2 RB76.1
N4932948: RT130.2 RT131.1
N4932950: RT131.2 RT132.1
N4932954: RB83.2 RB84.1
N4932956: RB84.2 RB85.1
N4932960: RT174.2 RT175.1
N4932962: RT175.2 RT176.1
N4932966: RB103.2 RB104.1
N4932968: RB104.2 RB105.1
N4932978: CT68.2 RB81.1 RT116.2 UT18.1
N4932986: CT68.1 RB79.2 RT116.1 RT118.1
N4932990: RT118.2 UT18.4
N4932994: RT114.2 UT18.3
N4933040: RT137.2 UT21.3
N4933044: CT86.2 RB82.1 RT141.2 UT21.1
N4933050: RT142.2 UT21.4
N4933092: RT180.2 UT32.3
N4933096: CT117.2 RB89.1 RT184.2 UT32.1
N4933102: RT191.2 UT32.4
N5087389: RT7.2 RT8.1
N5087393: RT8.2 RT9.1
N5087445: RT37.2 RT38.1
N5087449: RT38.2 RT39.1
N5087463: RT9.2 RT10.1
N5087477: RT39.2 RT40.1
N5215633: CT49.2 RT81.2 RT91.1 UT13.3
N5215739: CT46.2 RT82.2 RT83.1 UT13.1
N5215763: CT46.1 RT79.2 RT82.1 UT13.4
N5219233: CB47.1 UB16.5
N5220223: CT57.2 RT96.2 RT100.1 UT15.3
N5220393: CT55.2 RT98.2 RT99.1 UT15.1
N5220405: CT55.1 RT93.2 RT98.1 UT15.4
N5225791: CB6.1 UB1.1(VREF/2)
N5226417: CB69.1 UB21.1(VREF/2)
N5226863: CT59.1 UT16.5
N5227646: CT67.2 RT103.2 RT113.1 UT17.3
N5227670: CT64.2 RT104.2 RT105.1 UT17.1
N5227676: CT64.1 RT101.2 RT104.1 UT17.4
N5227730: CT75.2 RT119.2 RT122.1 UT19.3
N5227754: CT73.2 RT120.2 RT121.1 UT19.1
N5227760: CT73.1 RT115.2 RT120.1 UT19.4
N5284170: CT37.1 JT13.1(SIGNAL) RT66.2
N5287176: CT40.1 JT14.1(SIGNAL) RT75.2
N5307958: DT3.2 LT13.2 UT22.6 UT22.7 UT22.8 UT22.9 UT22.10 UT22.11
N5307974: CT88.1 DT3.1(C) QT1.1 QT1.2 QT1.3(S2) RT124.1 RT159.2
N5308194: DT2.C(CATHODE) QT1.4 RT124.2 UT22.3
N5308444: RT159.1 UT22.1
N5308460: RT146.1 RT147.1 UT22.13(~SHDN) UT24.3
N5308524: RT145.2 UT22.4
N5308650: RT144.2 UT22.14
N5308658: CT98.2 RT155.1 UT22.2
N5308734: CT97.2 UT22.15
N5308830: CT104.1 RT155.2
N5309781: CT100.1 RT161.2 UT24.1
N5377291: RT228.1 UT38.12
N5387179: CT152.2 LT27.1 UT38.18 UT38.20
N5387193: CT152.1 LT26.1 UT38.19(VISOOUT)
N5390614: RT227.1 UT38.9
N5390858: RT226.1 UT38.8
N5390867: RT225.1 UT38.6
N5429427: RT229.1 UT41.3
N5429751: CT157.1 RT230.1 RT247.2 UT41.1
N5430286: CB79.1 RB114.2 RB116.1 UT41.2 UT41.4
N5430623: CT158.1 RT233.1 RT249.2 UT41.5
N5431331: CT169.1 RT247.1
N5431438: CT170.1 RT249.1
N5432011: CT103.2 RT163.2 RT164.1 RT236.1
N5433071: QT5.3 RT248.2
N5433075: CT169.2 RT235.2 RT248.1
N5433096: CT170.2 QT5.2(E) RT234.1
N5433357: CT159.2 QT5.1 RT164.2 UT39.1
N5434399: CT159.1 RT236.2 UT39.4
N5434918: CB83.1 RB113.2 RB115.1 UT39.3
N5437148: CT162.1 RT237.1 RT250.2 UT43.1
N5437220: CT167.2 RT239.2 RT251.1
N5437228: CT167.1 RT250.1
N5437378: RT238.1 UT43.3
N5437474: CB81.1 RB117.2 RB120.1 UT43.2 UT43.4
N5437598: CT166.1 RT244.1 RT252.2 UT43.5
N5437614: QT4.3 RT251.2
N5437712: CB84.1 RB118.2 RB119.1 UT40.3
N5437790: CT165.2 QT4.1 RT246.2 UT40.1
N5437806: CT164.2 RT242.2 RT243.1 RT246.1
N5437826: CT165.1 RT243.2 UT40.4
N5437838: CT168.2 QT4.2(E) RT245.1
N5437898: CT168.1 RT252.1

Pads without a net: JT3 1 4 6 8; JT17 6; JT26 32 41 43 44 45 66 72 75 76 77 78 79 81 86 88 90 95 104 108 110 113 114 115 116 117 118 119 120 127 128 136 137 138 139 140 147 148 156 165 166 171 172 173 174 175 176 177 178; UB18 17 18; UB19 11 12 13 14 15; UB22 9 10; UT2 9 10 11 13 14 15; UT4 9 10 11 13 14 15; UT5 1; UT6 1; UT7 1; UT22 12; UT26 9 10 11 13 14 15; UT27 17 18; UT28 11 12 13 14 15; UT29 1; UT30 1; UT31 1; UT34 9 10 11 13 14 15; UT38 17; UT41 7 8; UT43 7 8

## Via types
v1: diameter 0.61, hole 0.33, TOP to BOTTOM, 648 vias
v2: diameter 3.175, hole 1.6, TOP to BOTTOM, 2 vias
v3: diameter 6.096, hole 3.302, TOP to BOTTOM, 2 vias

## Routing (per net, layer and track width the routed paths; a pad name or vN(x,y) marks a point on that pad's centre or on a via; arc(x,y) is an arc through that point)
+1V5REF: length 86.8
  TOP w0.508: CT58.1 53.55,66.8 UT16.1
  TOP w0.635: v1(51.44,91.98) RT73.1 ; v1(51.44,76.98) RT90.1 ; v1(51.44,61.98) RT112.1 ; v1(51.44,46.98) RT136.1 ; v1(51.44,106.98) RT61.1 ; CT58.1 52.45,66.65 52.32,66.78 v1(51.44,66.78) ; v1(51.44,31.98) RT173.1
  LAYER3 w0.635: v1(51.44,31.98) 51.44,37.45 51.44,37.45 51.44,46.23 v1(51.44,46.98) v1(51.44,61.98) v1(51.44,66.78) v1(51.44,76.98) v1(51.44,91.98) v1(51.44,106.98)
+1V5REF_RSLV: length 41.9
  TOP w0.508: v1(207.1,65.63) RT100.2 CT57.1 CT56.1 ; CT66.1 CT67.1 RT113.2 v1(207.1,58.28) ; CT48.1 CT49.1 RT91.2 v1(207.1,73.45) 207.1,73.43 ; CT74.1 CT75.1 RT122.2 v1(208.18,51.89)
  BOTTOM w0.508: v1(207.1,65.63) v1(207.1,73.45) ; v1(207.1,65.63) v1(207.1,58.28) 207.1,52.97 v1(208.18,51.89) ; v1(207.1,65.63) 208.62,65.63 CB46.1 208.87,65.58 UB16.1
+3V3: length 221.8
  TOP w0.254: RT238.2 v1(205.62,45.82) ; RT229.2 v1(205.41,37.16)
  TOP w0.381: RT54.2 177.24,105.86 v1(177.25,105.85) ; v1(196.99,43.43) CT163.1 198.89,44.13 198.89,44.55 199.33,44.98 UT40.5 ; UT8.16 95.94,113.61 96.43,113.12 CT31.1 v1(97.8,112.2) ; v1(81.01,32.57) CT108.1 79.03,32.2 UT26.16 ; v1(96.2,26.4) 95.93,26.66 UT25.16 94.51,26.3 CT126.1 ; v1(171.92,105.77) 171.9,105.79 RT53.2 ; UT38.4 202.59,101.91 202.3,101.62 CT156.1 CT33.1 v1(198.78,101.62) ; v1(197.91,33.36) 198.19,33.64 CT160.1 198.19,34.53 198.89,35.23 198.89,35.63 199.33,36.06 UT39.5 ; RT78.1 v1(198.61,82.03) ; UT2.16 80.1,129.29 CT2.1 v1(82.08,129.65) ; CT7.1 94.49,123.46 UT1.16 95.91,123.82 v1(96.17,123.55) ; v1(97.88,15.8) CT145.1 96.51,16.72 96.02,17.21 UT35.16 ; UT34.16 78.71,21.82 77.93,22.59 CT130.1 v1(76.56,23.22) ; v1(77.33,119.62) CT16.1 78.7,118.99 79.48,118.21 UT4.16 ; RT192.1 172.88,26.26 172.69,26.45 v1(172.69,27.07)
  TOP w0.508: v1(56.74,54.73) UT18.5 56.83,55.77 CT70.1 ; CT62.1 58.62,63.17 v1(58.81,63.36) 58.81,64.08 58,64.9 UT16.4 UT16.3 ; v1(56.74,84.73) UT11.5 56.83,85.77 CT42.1 ; CT89.1 56.83,40.77 UT21.5 v1(56.74,39.73) ; v1(56.74,69.73) UT14.5 56.83,70.77 CT52.1 ; v1(48.84,115.62) 48.84,116.74 UT3.5 48.92,116.66 CT21.1 ; CT36.1 56.83,100.77 UT10.5 v1(56.74,99.73) ; CT119.1 56.83,25.77 UT32.5 v1(56.74,24.73) ; CT51.1 200.05,71.66 UT15.5 200.53,72.11 v1(200.72,72.3) ; CT60.1 200.05,64.15 UT17.5 200.53,64.6 v1(200.72,64.78) ; v1(200.72,79.82) 200.53,79.63 UT13.5 200.05,79.18 CT43.1 ; v1(200.72,57.27) 200.53,57.08 UT19.5 200.05,56.63 CT69.1
  TOP w0.635: CT125.1 198.07,26.54 198.33,26.27 UT33.3
  PWR w0.381: UT33.3 199.53,27.22 ; UT33.3 198.57,26.27 ; UT33.3 200.28,25.52 ; UT33.3 200.48,26.27 ; UT33.3 199.53,25.32 ; UT33.3 198.78,25.52 ; UT33.3 198.78,27.02 ; UT33.3 200.28,27.02 ; 70.29,78.93 JT17.5 ; JT17.5 70.29,77.5 ; JT17.5 71.72,78.93 ; JT17.5 71.72,77.5 ; JT17.5 71,79.12 ; JT17.5 70.1,78.22 ; JT17.5 71.9,78.22 ; JT17.5 71,77.31 ; JT2.7 173.6,111.99 ; JT2.7 172.76,111.74 ; JT2.7 172.76,113.93 ; JT2.7 171.91,113.68 ; JT2.7 173.85,112.84 ; JT2.7 173.6,113.68 ; JT2.7 171.91,111.99 ; JT2.7 171.66,112.84
  BOTTOM w0.254: RB49.1 100.83,78.01 v1(101.89,78.01) CB29.1 103.02,77.99 102.27,77.24 UB11.8 ; UB3.8 82.43,91.5 83.18,92.25 CB12.1 v1(82.05,92.27) 80.99,92.27 RB29.1 ; UB3.3 86.12,89.86 v1(86.38,90.12) ; RB30.1 91.17,92.27 v1(92.23,92.27) CB13.1 93.36,92.25 92.61,91.5 UB4.8 ; v1(96.3,75.85) 96.04,75.6 UB10.3 ; UB9.8 82.43,77.24 83.18,77.99 CB27.1 v1(82.05,78.01) 80.99,78.01 RB47.1 ; RB31.1 101.34,92.27 v1(102.4,92.27) CB14.1 103.53,92.25 102.78,91.5 UB5.8 ; UB5.3 106.47,89.86 v1(106.73,90.12) ; UB9.3 86.12,75.6 v1(86.38,75.85) ; UB4.3 96.3,89.86 v1(96.55,90.12) ; UB11.3 105.96,75.6 v1(106.22,75.85) ; UB10.8 92.35,77.24 93.1,77.99 CB28.1 v1(91.97,78.01) 90.91,78.01 RB48.1
  BOTTOM w0.381: v1(205.41,37.16) 204.91,36.65 RB113.1 ; v1(161.22,65.51) CB43.1 160.4,66.61 160.06,66.95 158.94,66.95 158.65,66.66 UB15.5 ; v1(76.56,23.22) 77.19,22.6 RB110.1 ; v1(82.08,129.65) 80.43,129.65 79.16,128.38 79.16,128.21 78.69,127.75 RB2.1 ; RB3.1 96.9,124.28 v1(96.17,123.55) ; RB118.1 204.8,45.01 v1(205.62,45.82) ; RB27.2 v1(70.56,93.35) ; v1(172.69,27.07) CB72.1 172.69,29.31 UB22.1 ; v1(96.2,26.4) 96.92,27.12 RB95.1 ; RB91.1 77.62,30.66 78.09,31.13 78.09,31.3 79.36,32.57 v1(81.01,32.57) ; v1(97.88,15.8) 97.88,16.89 96.98,17.79 RB111.1 ; UB17.5 158.65,61.25 159.28,61.88 159.92,61.88 160.4,61.4 CB54.1 v1(161.22,60.23) ; UB20.5 158.11,40.36 157.73,40.74 156.28,40.74 155.84,40.3 CB68.1 154.72,40.3 154.44,40.58 v1(154.44,41.13) ; RB13.1 96.9,114.18 97.8,113.29 v1(97.8,112.2) ; RB6.1 77.95,118.99 v1(77.33,119.62)
  BOTTOM w0.508: CB8.1 76.94,101.3 v1(76.18,102.06) 75.68,102.06 UB2.5 ; UB12.5 79.95,67.39 v1(79.45,67.39) 78.69,68.16 CB37.1 ; UB14.5 99.79,67.39 v1(99.29,67.39) 98.53,68.16 CB39.1 ; UB13.5 89.87,67.39 v1(89.37,67.39) 88.61,68.16 CB38.1 ; UB7.5 90.12,81.66 v1(89.63,81.66) 88.86,82.42 CB22.1 ; UB8.5 100.3,81.66 v1(99.8,81.66) 99.04,82.42 CB23.1 ; UB21.3 UB21.4 141.6,34.04 142.41,33.23 v1(143.11,33.23) 143.33,33.44 CB70.1 ; CB21.1 78.69,82.42 v1(79.45,81.66) 79.95,81.66 UB6.5 ; UB1.3 UB1.4 145.97,109.74 145.16,110.55 v1(144.43,110.55) 144.25,110.37 CB5.1 ; UB16.3 UB16.4 213.56,67.95 v1(213.56,68.6) 212.95,69.21 CB36.1
+3VREF_A: length 30.9
  BOTTOM w0.508: 147.72,111.22 153.64,111.22 155.5,113.08 RB17.1 ; 147.72,111.22 144.91,114.03 RB16.1 143.33,113.98 141.76,112.4 131.91,112.4 131.16,113.15 RB15.1 ; 147.72,111.22 CB4.1 147.72,109.67 UB1.5
+3VREF_B: length 30.6
  BOTTOM w0.508: 132.46,29.19 135.86,32.59 CB71.1 ; 132.46,29.19 RB93.1 ; 132.46,29.19 131.17,30.49 120.76,30.49 120.29,30.02 RB92.1 ; CB71.1 139.85,32.57 140.76,31.66 142.16,31.66 144.63,29.19 RB94.1 ; CB71.1 139.85,34.12 UB21.5
+5V: length 107.2
  TOP w0.381: UT28.20 169.49,25.35 170.23,24.62 CT129.1 v1(170.23,22.5) ; UT31.4 142.09,25.26 142.06,25.29 CT123.1 141.24,24.44 140.98,24.19 v1(140.98,24.06) ; v1(161.62,22.4) CT128.1 161.62,24.62 160.95,25.29 UT27.20 ; v1(134.81,119.11) 134.81,118.98 134.56,118.73 CT22.1 133.74,117.88 133.7,117.91 UT5.4 ; RT193.1 178.34,26.33 v1(177.59,27.07) ; v1(194.5,32.41) RT166.1 RT172.1 ; v1(194.5,38.91) RT148.1 RT156.1 ; JT26.48 v1(104.83,48.78) ; v1(198.37,104.8) CT153.1 201.43,104.8 CT150.1 201.95,104.75 202.75,103.95 202.75,103.56 203.13,103.18 UT38.3 ; JT26.180 v1(181.12,48.77) ; v1(194.5,25.9) RT186.1 RT194.1 ; UT6.4 145.87,117.91 145.91,117.88 CT23.1 146.72,118.73 146.98,118.98 v1(146.98,119.11) ; v1(159.15,119.11) 159.15,118.98 158.89,118.73 CT24.1 158.07,117.88 158.04,117.91 UT7.4 ; UT29.4 117.76,25.26 117.72,25.29 CT121.1 116.9,24.44 116.65,24.19 v1(116.65,24.06) ; JT26.98 v1(128.04,48.78) ; JT26.112 v1(133.63,48.77) ; UT30.4 129.93,25.26 129.89,25.29 CT122.1 129.07,24.44 128.82,24.19 v1(128.82,24.06) ; v1(172.3,48.77) JT26.158 ; JT26.84 v1(122.43,48.78)
  TOP w0.635: CT146.1 198.23,14.18 198.33,14.08 UT36.3
  PWR2 w0.381: 178.91,13.48 179.67,14.23 ; 178.91,13.48 178.91,14.44 ; 178.91,13.48 179.88,13.48 ; 178.91,13.48 179.67,12.72 ; 178.91,13.48 177.95,13.48 ; 178.91,13.48 178.91,12.51 ; 178.91,13.48 178.15,14.23 ; 178.91,13.48 178.15,12.72 ; 183.02,29.37 JT41.4 ; JT41.4 183.26,28.52 ; JT41.4 184.11,30.46 ; JT41.4 184.11,28.28 ; JT41.4 184.96,30.22 ; JT41.4 184.96,28.52 ; JT41.4 183.26,30.22 ; JT41.4 185.2,29.37 ; 198.57,14.08 UT36.3 ; UT36.3 200.48,14.08 ; UT36.3 199.53,15.03 ; UT36.3 199.53,13.13 ; UT36.3 198.78,14.83 ; UT36.3 200.28,14.83 ; UT36.3 200.28,13.33 ; UT36.3 198.78,13.33 ; 186.65,35.9 JT41.9 ; JT41.9 187.5,36.14 ; JT41.9 187.5,37.84 ; JT41.9 185.56,36.99 ; JT41.9 186.65,38.08 ; JT41.9 187.74,36.99 ; JT41.9 185.8,37.84 ; JT41.9 185.8,36.14 ; 178.15,137.12 JB1.2 ; JB1.2 179.67,138.63 ; JB1.2 178.91,138.84 ; JB1.2 179.88,137.88 ; JB1.2 178.15,138.63 ; JB1.2 177.95,137.88 ; JB1.2 178.91,136.91 ; JB1.2 179.67,137.12
  BOTTOM w0.381: UB19.20 179.55,65.06 180.44,65.95 CB45.1 v1(180.44,68.04) ; v1(171.55,68.17) CB44.1 171.55,67.04 170.85,66.34 170.85,66.14 170.3,65.59 UB18.20 ; v1(177.59,27.07) CB73.1 178.09,28.68 UB22.24 UB22.23
+5V-ISO: length 16.2
  TOP w0.381: UT38.16 214.72,100.64 215.49,101.42 CT155.1 CT151.1 v1(218.56,101.42) ; v1(221.77,104.92) CT154.1 220.19,104.76 LT26.2
  PWR w0.381: JT3.9 231.17,104.16 ; JT3.9 229.36,104.16 ; JT3.9 229.55,104.88 ; JT3.9 229.55,103.45 ; JT3.9 230.98,103.45 ; JT3.9 230.98,104.88 ; JT3.9 230.27,103.26 ; JT3.9 230.27,105.06
+12V: length 582.4
  TOP w0.254: v1(220.94,8.97) 221.19,8.72 UT37.8 ; v1(217.89,6.1) 217.89,5.2
  TOP w0.381: 200.48,32.73 CT111.1 ; CT111.1 201.16,30.92 ; CT111.1 201.83,30.92 ; CT111.1 200.43,31.83 ; CT111.1 200.48,30.92 ; CT111.1 201.83,32.73 ; CT111.1 201.89,31.83 ; CT111.1 201.16,32.73 ; 232.51,48.55 DT2.A ; DT2.A 233.5,47.93 ; DT2.A 232.56,47.93 ; DT2.A 233.55,48.55 ; DT2.A 233.03,47.93 ; 218.21,3.49 RT220.2 ; RT220.2 216.31,4.32 ; RT220.2 220.11,5.02 ; RT220.2 216.31,5.02 ; RT220.2 218.21,5.14 ; RT220.2 216.31,3.62 ; RT220.2 220.11,4.32 ; RT220.2 220.11,3.62 ; 237.08,45.25 LT13.1 ; LT13.1 238.86,47.45 ; LT13.1 238.98,45.25 ; LT13.1 238.03,43.04 ; LT13.1 237.2,47.45 ; LT13.1 238.03,47.45 ; LT13.1 237.2,43.04 ; LT13.1 238.86,43.04 ; UT33.1 199.53,22.14 ; UT33.1 199.53,20.24 ; UT33.1 200.48,20.24 ; UT33.1 200.48,21.19 ; UT33.1 200.48,22.14 ; 199.53,8.05 UT36.1 ; UT36.1 200.48,9 ; UT36.1 200.48,8.05 ; UT36.1 199.53,9.95 ; UT36.1 200.48,9.95
  TOP w0.508: v1(224.7,37.52) RT146.2
  TOP w0.635: CT134.1 198.15,21 198.33,21.19 UT33.1 ; UT36.1 198.33,9 198.11,8.78 CT147.1
  LAYER3 w0.254: v1(217.89,6.1) 218.19,6.1 220.94,8.85 v1(220.94,8.97)
  LAYER3 w0.508: v1(224.7,37.52) 224.7,47.3 226.7,49.31 235.83,49.31 v1(235.84,49.3)
  BOTTOM w0.381: UT33.1 200.48,21.19 ; UT33.1 200.48,20.24 ; UT33.1 199.53,20.24 ; UT33.1 200.48,22.14 ; UT33.1 199.53,22.14 ; UT36.1 200.48,9.95 ; UT36.1 199.53,8.05 ; UT36.1 200.48,8.05 ; UT36.1 199.53,9.95 ; UT36.1 200.48,9
  BOTTOM w1.27: 73.06,142.78 102.85,142.78 103.75,141.88 103.75,139.89 102.09,138.23 JB4.1 104.24,135.72 112.13,135.72 120.36,127.49 158.4,127.49 161.55,124.34 161.55,115.22 163.94,112.84 JT2.1 165.14,105.42 170.75,99.81 191.42,99.81 193.58,97.65 193.58,44.18 195.89,41.87 195.89,32.02 198.31,29.61 199.04,29.61 199.55,29.09 ; 73.06,142.78 74.33,141.51 74.33,140.06 73.06,138.79 72.45,138.79 JB3.1 ; 73.06,142.78 45.68,142.78 44.05,141.16 44.05,139.2 43.08,138.23 JB2.1 ; JB7.1 52.46,6.77 51.52,5.83 51.52,1.91 51.67,1.76 ; 81.39,1.76 51.67,1.76 ; 81.39,1.76 81.29,1.87 81.29,5.87 82.18,6.77 JB8.1 ; 81.39,1.76 102.83,1.76 117.66,16.59 126.96,16.59 141.79,1.76 179.18,1.76 186.09,8.67 194.29,8.67 196.22,6.74 203.86,6.74 204.27,6.33 ; 51.67,1.76 23.15,1.76 21.88,3.03 21.88,5.67 22.98,6.77 JB6.1
  vias: v1(201.63,12.8) v1(201.63,10.26) v1(201.63,7.72) v1(201.63,5.18) v1(201.63,2.64) v1(204.17,12.8) v1(204.17,10.26) v1(204.17,7.72) v1(204.17,5.18) v1(204.17,2.64) v1(206.71,12.8) v1(206.71,10.26) v1(206.71,7.72) v1(206.71,5.18) v1(206.71,2.64) v1(209.25,12.8) v1(209.25,10.26) v1(209.25,7.72) v1(209.25,5.18) v1(209.25,2.64)
+15V: length 194.1
  TOP w0.254: CT95.1 v1(215.83,37.51) UT41.11 ; UT41.12 UT41.11 ; UT41.11 UT41.10 ; UT43.11 v1(216.04,46.17) CT161.1 ; UT43.11 UT43.10 ; UT43.11 UT43.12
  TOP w0.381: v1(213.6,55.83) 213.9,55.83 213.91,55.82 DT10.2 ; 220.91,45.63 QT1.7 ; QT1.7 220.92,45.1 ; QT1.7 221.94,46.15 ; QT1.7 221.43,46.15 ; QT1.7 221.94,45.1 ; QT1.7 221.43,45.1 ; QT1.7 220.92,46.15 ; QT1.7 221.95,45.63 ; DT11.5 v1(217.38,63.33) ; QT1.5 221.94,47.64 ; QT1.5 221.43,48.69 ; QT1.5 220.92,48.69 ; QT1.5 220.91,48.17 ; QT1.5 221.95,48.17 ; QT1.5 221.94,48.69 ; QT1.5 221.43,47.64 ; QT1.5 220.92,47.64 ; QT1.6 221.95,46.9 ; QT1.6 221.94,46.37 ; QT1.6 221.43,47.42 ; QT1.6 220.91,46.9 ; QT1.6 221.43,46.37 ; QT1.6 220.92,46.37 ; QT1.6 220.92,47.42 ; QT1.6 221.94,47.42 ; QT1.8 221.94,44.88 ; QT1.8 220.92,43.83 ; QT1.8 220.91,44.36 ; QT1.8 220.92,44.88 ; QT1.8 221.43,43.83 ; QT1.8 221.94,43.83 ; QT1.8 221.43,44.88 ; QT1.8 221.95,44.36 ; CT87.1 222.05,43.12 ; CT87.1 221.34,43.12 ; CT87.1 220.64,43.12 ; CT87.1 222.12,42.02 ; CT87.1 220.57,42.02 ; DT14.5 v1(217.38,78.36) ; DT13.2 v1(213.6,70.85) ; v1(237.7,75.1) DT15.2 ; DT13.5 v1(217.38,70.85) ; DT10.5 v1(217.38,55.82) ; DT14.2 v1(213.6,78.36) ; v1(213.6,63.33) DT11.2 ; DT15.5 v1(241.49,75.1) ; DT12.5 v1(241.49,58.44) ; v1(237.7,58.44) DT12.2 ; v1(201.34,41.85) 201.34,41.51 RT235.1 ; RT239.1 v1(201.27,49.53)
  TOP w0.635: v1(219.84,41.89) 221.22,41.89 CT87.1 ; 220.74,43.76 220.74,43.52 220.38,43.16 v1(219.79,43.16)
  BOTTOM w0.381: v1(237.7,58.44) v1(237.7,75.1) 238.14,75.54 238.15,75.54 238.39,75.77 240.81,75.77 v1(241.49,75.1) ; v1(237.7,58.44) 229.33,50.07 225.66,50.07 v1(224.54,48.95) 224.48,49 223.91,49 220.02,52.9 214.74,52.9 213.6,54.04 v1(213.6,55.83) ; v1(237.7,58.44) 238.4,57.75 240.79,57.75 v1(241.49,58.44) ; v1(213.6,55.83) 214.3,55.12 216.68,55.12 v1(217.38,55.82) ; v1(213.6,55.83) v1(213.6,63.33) 214.26,62.67 216.72,62.67 v1(217.38,63.33) v1(217.38,70.85) ; v1(217.38,70.85) v1(217.38,78.36) 216.71,77.69 214.27,77.69 v1(213.6,78.36) ; v1(217.38,70.85) 216.71,70.18 214.27,70.18 v1(213.6,70.85) ; 204.29,39.86 RB114.1
  BOTTOM w0.508: v1(216.04,46.17) 216.04,48.57 214.42,50.19 204.83,50.19 204.34,49.7 RB117.1 202.04,48.76 v1(201.27,49.53) ; 215.81,41.39 205.82,41.39 204.29,39.86 203.33,39.86 v1(201.34,41.85)
  BOTTOM w0.635: v1(216.04,46.17) 219.05,43.16 v1(219.79,43.16) 219.79,41.94 v1(219.84,41.89) 216.31,41.89 215.81,41.39 215.83,41.37 v1(215.83,37.51)
VIN: length 68.8
  TOP w0.178: 230.53,14.23 QT3.6 ; QT3.6 229.99,13.67 ; QT3.6 230.53,13.12 ; 229.99,12.4 QT3.5 230.53,12.96 ; QT3.7 230.53,14.39 ; QT3.7 229.99,14.94 ; QT3.7 230.53,15.5 ; QT3.8 230.53,15.66
  TOP w0.254: UT37.1 227.42,7.7 v1(227.92,7.2) ; RT223.1 v1(224.62,3.39)
  TOP w0.381: 230.53,13.15 QT3.6 ; QT3.6 230.01,13.67 ; QT3.6 231.05,13.67 ; QT3.6 231.04,14.2 ; QT3.6 230.53,14.2 ; QT3.6 231.04,13.15 ; QT3.6 230.02,13.15 ; QT3.6 230.02,14.2 ; QT3.8 231.04,15.69 ; QT3.8 231.04,16.74 ; QT3.8 230.53,16.74 ; QT3.8 230.02,16.74 ; QT3.8 231.05,16.21 ; QT3.8 230.02,15.69 ; QT3.8 230.53,15.69 ; QT3.8 230.01,16.21 ; QT3.7 231.05,14.94 ; QT3.7 231.04,14.42 ; QT3.7 230.01,14.94 ; QT3.7 231.04,15.47 ; QT3.7 230.53,14.42 ; QT3.7 230.02,15.47 ; QT3.7 230.02,14.42 ; QT3.7 230.53,15.47 ; 235.11,23.93 JT42.1 ; JT42.1 235.11,29.32 ; JT42.1 235.11,26.63 ; JT42.1 237.91,29.33 ; JT42.1 240.72,29.32 ; JT42.1 240.72,23.93 ; JT42.1 237.91,23.92 ; JT42.1 240.72,26.63 ; 228.5,10.24 RT217.1 ; RT217.1 228.52,10.95 ; RT217.1 229.81,10.24 ; RT217.1 229.16,10.95 ; RT217.1 229.79,10.95 ; 230.53,11.88 QT3.5 ; QT3.5 231.04,11.88 ; QT3.5 230.02,11.88 ; QT3.5 230.01,12.4 ; QT3.5 230.02,12.93 ; QT3.5 230.53,12.93 ; QT3.5 231.04,12.93 ; QT3.5 231.05,12.4
  LAYER3 w0.254: v1(224.62,3.39) 224.62,3.89 v1(227.92,7.2) 226.91,8.21 v1(226.91,11.9)
0: length 1837.4
  TOP w0.254: v1(218.98,38.34) 218.98,38.19 218.33,37.53 CT95.2 ; CT149.2 v1(221.41,3.64) ; RT234.2 v1(200.96,34.49) ; v1(226.3,10.37) 226.53,10.14 UT37.5 ; RT245.2 v1(201.16,43.16) ; v1(226.53,2.88) CT148.2 226.67,4.4 227.88,4.4 229.16,5.68 RT221.2 ; CT161.2 218.53,46.2 219.18,46.85 v1(219.18,47.01)
  TOP w0.381: JT26.22 94.44,48.75 v1(94.42,48.77) ; CT118.2 CT116.2 v1(194.5,29.15) ; DT13.4 216.07,70.2 215.49,70.78 v1(215.49,70.85) 215.49,70.87 214.86,71.5 DT13.1 ; v1(140.63,118.35) 140.2,117.91 UT6.11 ; UT38.2 UT38.1 203.34,105.72 v1(202.93,106.13) 202.71,106.35 CT150.2 201.23,106.6 CT153.2 ; CT124.2 101.6,24.91 100.87,25.64 98.85,25.64 98.47,25.25 v1(97.85,25.25) CT126.2 ; CT91.2 v1(194.5,40.54) ; UT27.19 160.3,23.76 CT128.2 v1(160.02,22.34) ; v1(89.63,48.78) 89.64,48.77 JT26.10 ; CT141.2 v1(150.13,18.73) ; v1(200.96,34.49) 200.94,34.51 CT160.2 ; JT14.2 187.82,87.85 CT40.2 ; JT26.65 v1(115.24,44.04) ; v1(198.99,46.72) UT40.2 ; CT13.1 v1(157.62,124.44) ; CT6.2 101.58,122.07 100.85,122.8 98.83,122.8 98.45,122.41 v1(97.83,122.41) CT7.2 ; v1(93,121.4) CT5.2 93.09,122.41 ; 93.11,25.25 CT120.2 v1(93.02,24.24) ; CT100.2 v1(225.75,34.59) ; 216.31,26.28 JT42.3 ; JT42.3 219.01,22.17 ; JT42.3 216.31,22.23 ; JT42.3 216.31,24.25 ; JT42.3 219.01,26.33 ; JT42.3 221.72,26.28 ; JT42.3 221.72,22.23 ; JT42.3 221.72,24.25 ; CT3.2 93.02,130.2 94.07,129.15 v1(97.8,129.15) 98.58,129.15 99.36,128.37 UT1.8 100.55,129.17 101.55,130.18 CT4.2 ; UT30.3 UT30.2 130.04,26.58 129.72,26.89 CT122.2 v1(129.07,28.13) ; v1(146.72,115.04) CT23.2 146.07,116.28 145.76,116.59 UT6.2 UT6.3 ; v1(93.36,111.57) 93.99,112.2 CT31.2 ; RT226.2 RT227.2 200.12,94.57 200.52,94.17 v1(202.73,94.17) 202.85,94.29 UT38.10 ; JT26.97 v1(128.04,44.38) ; JT26.135 163.52,44.68 163.56,44.64 v1(163.56,44.4) ; JT26.83 122.43,44.5 122.39,44.46 v1(122.39,44.4) ; v1(198.78,103.22) CT33.2 CT156.2 ; JT26.35 v1(100.02,44.4) ; UT31.3 UT31.2 142.2,26.58 141.89,26.89 CT123.2 v1(141.24,28.13) ; DT10.1 215.05,56.47 215.44,56.07 v1(215.44,55.8) 216.08,55.17 DT10.4 ; UT24.2 221.38,37.33 v1(221.47,37.23) RT160.2 ; CT164.1 v1(190.93,49.24) ; DT8.2 176.21,19.96 176.19,19.98 v1(175.56,19.98) DT7.2 ; JT42.2 219.01,31.08 ; JT42.2 216.31,29 ; JT42.2 216.31,26.98 ; JT42.2 221.72,31.03 ; JT42.2 221.72,29 ; JT42.2 219.01,26.92 ; JT42.2 221.72,26.98 ; JT42.2 216.31,31.03 ; CT139.2 v1(137.96,18.73) ; UT28.1 168.89,31.2 168.89,30.35 168.68,30.14 166.62,30.14 166.41,30.35 166.41,31.2 UT28.5 UT28.6 UT28.7 UT28.8 UT28.9 UT28.10 161.96,31.25 v1(161.94,31.23) 161.91,31.25 UT27.1 UT27.2 UT27.3 ; v1(123,24.82) 123.43,25.26 UT29.11 ; CT14.2 76.74,122.28 v1(77.12,122.66) 76.1,123.69 UT2.8 ; DT11.4 215.84,62.68 215.54,62.99 v1(215.54,63.39) 214.95,63.98 DT11.1 ; UT5.11 128.03,117.91 v1(128.46,118.35) ; CT145.2 94.07,15.8 v1(93.43,15.17) ; JT26.19 v1(93.62,44.38) ; CT127.2 75.67,25.2 v1(76.05,25.58) 75.03,26.61 UT26.8 ; UT29.3 UT29.2 117.87,26.58 117.55,26.89 CT121.2 v1(116.9,28.13) ; v1(172.3,44.31) JT26.157 ; v1(152.8,118.35) 152.36,117.91 UT7.11 ; JT26.179 v1(181.12,44.4) ; UT5.3 UT5.2 133.59,116.59 133.91,116.28 CT22.2 v1(134.56,115.04) ; CT1.2 v1(77.25,129.65) CT2.2 ; CT37.2 187.98,93.72 JT13.2 ; v1(147.33,24.82) 147.77,25.26 UT31.11 ; DT14.1 214.86,79.01 215.44,78.44 215.44,78.42 v1(215.49,78.36) 215.49,78.1 215.87,77.71 DT14.4 ; CT137.2 v1(125.79,18.73) ; JT26.111 v1(133.63,44.38) ; JT26.47 v1(104.83,44.4) ; v1(135.17,24.82) 135.6,25.26 UT30.11 ; CT140.1 v1(142.51,18.73) ; UT39.2 v1(198.99,37.8) ; UT27.10 155.1,31.71 v1(154.44,32.37) ; v1(75.8,112.78) 74.93,113.66 UT4.8 ; CT11.1 v1(145.45,124.44) ; CT103.1 v1(190.96,43.73) ; CT16.2 v1(81.52,119.62) ; DT12.4 240.22,57.79 239.59,58.41 v1(239.59,58.44) 239.59,58.47 238.97,59.09 DT12.1 ; DT4.2 DT5.2 ; DT5.2 175.61,28.26 v1(174.29,26.95) ; DT5.2 DT6.2 ; v1(194.5,35.66) CT99.2 CT106.2 ; CT110.2 101.58,33.02 100.57,32.01 UT25.8 99.38,31.21 98.61,31.99 v1(97.83,31.99) 94.1,31.99 93.05,33.04 CT109.2 ; JT26.46 v1(104.04,48.78) ; JT26.38 v1(100.84,48.77) ; v1(201.16,43.16) 200.89,43.43 CT163.2 ; v1(168.63,22.46) CT129.2 168.3,23.81 UT28.19 ; CT12.2 v1(150,124.44) ; CT130.2 v1(80.75,23.22) ; DT15.1 238.97,75.75 239.59,75.13 v1(239.59,75.1) 239.59,74.79 239.94,74.45 DT15.4 ; CT131.2 v1(194.5,22.64) ; JT26.16 v1(92.02,48.77) ; CT138.1 v1(130.34,18.73) ; CT107.2 v1(76.18,32.57) CT108.2 ; RT225.2 v1(199.1,99.3) ; UT7.3 UT7.2 157.92,116.59 158.24,116.28 CT24.2 v1(158.89,115.04) ; JT26.7 v1(88.82,44.44) ; v1(75.04,16.39) 74.16,17.27 UT34.8 ; JT26.29 v1(97.64,44.4) ; UT35.8 v1(100.6,22.86) ; CT136.1 v1(118.17,18.73) ; CT9.1 v1(133.29,124.44) ; CT8.2 v1(125.67,124.44) ; UT8.8 v1(100.52,119.26) ; CT10.2 v1(137.83,124.44) ; JT26.13 v1(91.24,44.38)
  TOP w0.508: v1(43.53,122.63) RT27.1 ; v1(51.7,118.26) 50.43,118.26 CT21.2 ; UT18.2 55.79,60.34 CT65.1 56.09,60.65 v1(57.29,60.65) ; CT60.2 196.15,64.15 v1(195.89,63.89) 195.89,62.89 CT63.2 ; CT111.2 199.36,33.19 199.79,33.63 CT160.2 ; UT10.2 55.79,105.34 CT34.1 56.09,105.65 v1(57.29,105.65) ; UT13.2 v1(201.48,74.86) 202.91,74.86 204.08,76.03 CT48.2 ; UT32.2 55.79,30.34 CT112.1 56.09,30.65 v1(57.29,30.65) ; CT51.2 196.15,71.66 v1(195.89,71.41) 195.89,70.4 CT54.2 ; CT43.2 196.15,79.18 v1(195.89,78.93) 195.89,77.92 CT45.2 ; v1(57.29,75.65) 56.09,75.65 CT47.1 55.79,75.34 UT14.2 ; CT89.2 v1(59.6,42.37) ; CT56.2 204.08,68.52 202.91,67.35 v1(201.48,67.35) UT15.2 ; UT17.2 v1(201.48,59.83) 202.91,59.83 204.08,61 CT66.2 ; CT52.2 v1(59.6,72.37) ; v1(57.29,90.65) 56.09,90.65 CT39.1 55.79,90.34 UT11.2 ; CT119.2 v1(59.6,27.37) ; CT42.2 v1(59.6,87.37) ; CT36.2 v1(59.6,102.37) ; UT3.2 47.89,121.23 CT15.1 49.29,121.52 v1(49.54,121.27) ; CT59.2 59.43,65.05 58.68,65.79 58.21,65.79 58.15,65.85 UT16.2 54.2,65.85 CT58.2 53.4,63.84 v1(53.81,63.43) 54.07,63.17 CT62.2 ; UT19.2 v1(201.48,52.32) 202.91,52.32 204.08,53.49 CT74.2 ; CT70.2 v1(59.6,57.37) ; CT69.2 196.15,56.63 v1(195.89,56.38) 195.89,55.37 CT72.2 ; v1(57.29,45.65) 56.09,45.65 CT81.1 55.79,45.34 UT21.2
  TOP w0.635: CT147.2 CT146.2 198.68,12.38 UT36.2 ; UT33.2 198.52,24.74 CT125.2 CT134.2
  GND1 w0.381: JT4.2 139.41,105.82 ; JT4.2 139.6,106.54 ; JT4.2 138.69,107.44 ; JT4.2 137.98,105.82 ; JT4.2 137.79,106.54 ; JT4.2 138.69,105.63 ; JT4.2 137.98,107.25 ; 67.56,75.67 JT17.4 ; JT17.4 69.18,74.96 ; JT17.4 69.18,76.39 ; JT17.4 68.46,74.77 ; JT17.4 68.46,76.58 ; JT17.4 69.36,75.67 ; JT17.4 67.75,76.39 ; JT17.4 67.75,74.96 ; JB3.2 72.74,139.92 ; JB3.2 71.04,139.92 ; JB3.2 71.04,141.62 ; JB3.2 70.8,140.77 ; JB3.2 71.89,141.86 ; JB3.2 72.98,140.77 ; JB3.2 71.89,139.68 ; JB3.2 72.74,141.62 ; JT6.5 88.56,105.7 ; JT6.5 88.01,106.41 ; JT6.5 86.94,106.41 ; JT6.5 87.85,107.31 ; JT6.5 87.85,105.51 ; JT6.5 87.13,107.12 ; JT6.5 87.13,105.7 ; 89.03,139.68 JB4.12 ; JB4.12 88.19,141.62 ; JB4.12 90.13,140.77 ; JB4.12 89.88,139.92 ; JB4.12 87.94,140.77 ; JB4.12 89.03,141.86 ; JB4.12 88.19,139.92 ; JB4.12 89.88,141.62 ; JT27.5 189.28,53.9 ; JT27.5 188.37,53 ; JT27.5 189.09,53.18 ; JT27.5 187.66,53.18 ; JT27.5 187.66,54.61 ; JT27.5 187.47,53.9 ; JT27.5 188.37,54.8 ; JT4.5 141.95,105.82 ; JT4.5 141.95,107.25 ; JT4.5 141.23,107.44 ; JT4.5 142.14,106.54 ; JT4.5 140.33,106.54 ; JT4.5 140.52,105.82 ; JT4.5 141.23,105.63 ; JT19.3 191.63,78.27 ; JT19.3 190.91,78.08 ; JT19.3 190.2,79.7 ; JT19.3 190.01,78.98 ; JT19.3 191.63,79.7 ; JT19.3 190.91,79.89 ; JT19.3 191.82,78.98 ; 70.16,49.69 JT28.3 ; JT28.3 69.97,50.4 ; JT28.3 71.78,50.4 ; JT28.3 70.88,49.5 ; JT28.3 71.59,51.12 ; JT28.3 70.88,51.3 ; JT28.3 71.59,49.69 ; 93.94,108.95 93.94,109.85 ; 93.94,108.95 93.04,108.95 ; 93.94,108.95 93.94,108.05 ; 93.94,108.95 93.23,109.66 ; 93.94,108.95 94.84,108.95 ; 93.94,108.95 94.66,109.66 ; 93.94,108.95 93.23,108.24 ; JT37.2 112.94,38.8 ; JT37.2 113.13,38.08 ; JT37.2 111.52,37.37 ; JT37.2 111.33,38.08 ; JT37.2 112.23,38.98 ; JT37.2 112.23,37.18 ; JT37.2 111.52,38.8 ; JB7.2 54.11,5.32 ; JB7.2 53.26,3.38 ; JB7.2 54.96,5.08 ; JB7.2 54.96,3.38 ; JB7.2 53.02,4.23 ; JB7.2 54.11,3.14 ; JB7.2 55.2,4.23 ; JB7.2 53.26,5.08 ; JT17.8 69.36,80.75 ; JT17.8 67.56,80.75 ; JT17.8 69.18,81.47 ; JT17.8 69.18,80.04 ; JT17.8 67.75,80.04 ; JT17.8 68.46,81.66 ; JT17.8 67.75,81.47 ; JT17.8 68.46,79.85 ; JT38.3 125.76,37.99 ; JT38.3 124.85,38.89 ; JT38.3 123.95,37.99 ; JT38.3 124.14,38.71 ; JT38.3 124.85,37.09 ; JT38.3 125.57,37.28 ; JT38.3 125.57,38.71 ; 148.48,34.74 JT40.4 ; JT40.4 149.9,34.74 ; JT40.4 149.19,34.55 ; JT40.4 149.9,36.17 ; JT40.4 150.09,35.45 ; JT40.4 148.29,35.45 ; JT40.4 149.19,36.35 ; JB3.14 57.5,139.92 ; JB3.14 56.65,139.68 ; JB3.14 57.74,140.77 ; JB3.14 57.5,141.62 ; JB3.14 55.8,141.62 ; JB3.14 55.56,140.77 ; JB3.14 56.65,141.86 ; JB3.14 55.8,139.92 ; JT4.4 141.95,109.79 ; JT4.4 141.23,109.98 ; JT4.4 141.23,108.17 ; JT4.4 141.95,108.36 ; JT4.4 140.33,109.08 ; JT4.4 140.52,109.79 ; JT4.4 142.14,109.08 ; 100.04,108.95 100.04,109.85 ; 100.04,108.95 99.32,108.24 ; 100.04,108.95 99.32,109.66 ; 100.04,108.95 100.94,108.95 ; 100.04,108.95 100.04,108.05 ; 100.04,108.95 100.75,109.66 ; 100.04,108.95 99.14,108.95 ; 67.62,39.78 JT30.4 ; JT30.4 68.34,39.59 ; JT30.4 68.34,41.4 ; JT30.4 69.05,39.78 ; JT30.4 67.62,41.21 ; JT30.4 69.24,40.5 ; JT30.4 67.43,40.5 ; JT39.3 137.92,37.99 ; JT39.3 136.31,38.71 ; JT39.3 137.02,37.09 ; JT39.3 137.74,37.28 ; JT39.3 137.74,38.71 ; JT39.3 137.02,38.89 ; JT39.3 136.12,37.99 ; 95.77,34.83 JT34.4 ; JT34.4 97.2,34.83 ; JT34.4 96.48,36.44 ; JT34.4 95.58,35.54 ; JT34.4 97.2,36.26 ; JT34.4 96.48,34.64 ; JT34.4 97.38,35.54 ; 98.1,4.23 JB8.14 ; JB8.14 100.29,4.23 ; JB8.14 99.19,5.32 ; JB8.14 100.04,5.08 ; JB8.14 98.35,3.38 ; JB8.14 99.19,3.14 ; JB8.14 100.04,3.38 ; JB8.14 98.35,5.08 ; JT31.2 71.59,37.37 ; JT31.2 70.16,38.8 ; JT31.2 71.78,38.08 ; JT31.2 69.97,38.08 ; JT31.2 70.88,37.18 ; JT31.2 70.88,38.98 ; JT31.2 71.59,38.8 ; 198.78,22.98 UT33.2 ; UT33.2 200.48,23.73 ; UT33.2 198.57,23.73 ; UT33.2 200.28,22.98 ; UT33.2 198.78,24.48 ; UT33.2 200.28,24.48 ; UT33.2 199.53,22.78 ; UT33.2 199.53,24.68 ; JT25.4 69.24,55.36 ; JT25.4 67.43,55.36 ; JT25.4 67.62,54.64 ; JT25.4 68.34,54.45 ; JT25.4 67.62,56.07 ; JT25.4 69.05,54.64 ; JT25.4 68.34,56.26 ; 112.23,108.95 113.13,108.95 ; 112.23,108.95 112.23,108.05 ; 112.23,108.95 112.23,109.85 ; 112.23,108.95 112.94,109.66 ; 112.23,108.95 111.33,108.95 ; 112.23,108.95 111.52,109.66 ; 112.23,108.95 111.52,108.24 ; JT35.2 100.94,38.08 ; JT35.2 99.32,37.37 ; JT35.2 99.32,38.8 ; JT35.2 99.14,38.08 ; JT35.2 100.04,38.98 ; JT35.2 100.75,38.8 ; JT35.2 100.04,37.18 ; JT27.3 191.63,55.72 ; JT27.3 190.2,57.15 ; JT27.3 191.63,57.15 ; JT27.3 191.82,56.44 ; JT27.3 190.91,55.54 ; JT27.3 190.91,57.34 ; JT27.3 190.01,56.44 ; 101.86,38.8 JT35.3 ; JT35.3 103.29,38.8 ; JT35.3 102.58,37.18 ; JT35.3 103.48,38.08 ; JT35.3 102.58,38.98 ; JT35.3 103.29,37.37 ; JT35.3 101.68,38.08 ; JB6.14 39.5,5.32 ; JB6.14 40.35,3.38 ; JB6.14 38.66,5.08 ; JB6.14 40.35,5.08 ; JB6.14 40.6,4.23 ; JB6.14 39.5,3.14 ; JB6.14 38.66,3.38 ; JB6.14 38.41,4.23 ; JT5.4 84.29,107.31 ; JT5.4 83.39,106.41 ; JT5.4 83.58,105.7 ; JT5.4 85,105.7 ; JT5.4 84.29,105.51 ; JT5.4 85.19,106.41 ; JT5.4 85,107.12 ; JB6.2 25.11,5.08 ; JB6.2 24.26,5.32 ; JB6.2 25.36,4.23 ; JB6.2 23.42,5.08 ; JB6.2 23.17,4.23 ; JB6.2 25.11,3.38 ; JB6.2 23.42,3.38 ; JB6.2 24.26,3.14 ; 67.62,61.02 JT24.4 ; JT24.4 69.24,60.31 ; JT24.4 68.34,61.21 ; JT24.4 67.43,60.31 ; JT24.4 68.34,59.41 ; JT24.4 67.62,59.59 ; JT24.4 69.05,59.59 ; 114.77,108.95 114.77,109.85 ; 114.77,108.95 114.06,109.66 ; 114.77,108.95 113.87,108.95 ; 114.77,108.95 115.48,108.24 ; 114.77,108.95 115.48,109.66 ; 114.77,108.95 115.67,108.95 ; 114.77,108.95 114.77,108.05 ; JT5.5 82.46,105.7 ; JT5.5 81.75,105.51 ; JT5.5 81.75,107.31 ; JT5.5 80.85,106.41 ; JT5.5 81.04,105.7 ; JT5.5 81.04,107.12 ; JT5.5 82.48,106.41 ; 190.85,16.62 JB5.S1 ; JB5.S1 192.32,18.1 ; JB5.S1 190.85,19.57 ; JB5.S1 189.73,19.22 ; JB5.S1 191.97,19.22 ; JB5.S1 191.97,16.98 ; JB5.S1 189.38,18.1 ; JT21.4 71.59,65.97 ; JT21.4 69.97,65.26 ; JT21.4 70.88,66.16 ; JT21.4 70.88,64.36 ; JT21.4 70.16,64.55 ; JT21.4 71.78,65.26 ; JT21.4 71.59,64.55 ; JB2.2 42.89,141.62 ; JB2.2 43.14,140.77 ; JB2.2 40.95,140.77 ; JB2.2 42.04,141.86 ; JB2.2 42.89,139.92 ; JB2.2 41.2,141.62 ; JB2.2 42.04,139.68 ; JB2.2 41.2,139.92 ; 93.23,36.26 JT34.5 ; JT34.5 94.66,34.83 ; JT34.5 93.94,34.64 ; JT34.5 93.94,36.44 ; JT34.5 93.04,35.54 ; JT34.5 94.84,35.54 ; JT34.5 93.23,34.83 ; 182.4,53.58 JT26.G4 ; JT26.G4 183.25,52.73 ; JT26.G4 183.93,54.26 ; JT26.G4 182.57,52.9 ; JT26.G4 184.1,53.58 ; JT26.G4 183.25,54.44 ; JT26.G4 182.57,54.26 ; JT26.G4 183.93,52.9 ; JT9.4 108.67,107.31 ; JT9.4 107.96,105.7 ; JT9.4 109.39,107.12 ; JT9.4 107.77,106.41 ; JT9.4 109.58,106.41 ; JT9.4 108.67,105.51 ; JT9.4 109.39,105.7 ; 81.04,37.37 JT32.2 ; JT32.2 81.75,38.98 ; JT32.2 82.46,38.8 ; JT32.2 81.75,37.18 ; JT32.2 81.04,38.8 ; JT32.2 82.65,38.08 ; JT32.2 80.85,38.08 ; 102.58,108.05 102.58,108.95 ; 102.58,108.95 103.29,108.24 ; 102.58,108.95 102.58,109.85 ; 102.58,108.95 101.86,109.66 ; 102.58,108.95 101.68,108.95 ; 102.58,108.95 103.29,109.66 ; 102.58,108.95 103.48,108.95 ; JB7.12 67.9,4.23 ; JB7.12 67.66,3.38 ; JB7.12 66.81,3.14 ; JB7.12 65.96,5.08 ; JB7.12 67.66,5.08 ; JB7.12 65.72,4.23 ; JB7.12 65.96,3.38 ; JB7.12 66.81,5.32 ; JT39.5 135.38,35.45 ; JT39.5 133.77,34.74 ; JT39.5 135.2,34.74 ; JT39.5 133.58,35.45 ; JT39.5 134.48,34.55 ; JT39.5 134.48,36.35 ; JT39.5 133.77,36.17 ; JT17.10 68.46,84.2 ; JT17.10 68.46,82.39 ; JT17.10 69.18,84.01 ; JT17.10 67.75,82.58 ; JT17.10 69.36,83.3 ; JT17.10 67.75,84.01 ; JT17.10 67.56,83.3 ; JT17.10 69.18,82.58 ; 81.75,108.95 81.75,109.85 ; 81.75,108.95 81.04,108.24 ; 81.75,108.95 82.48,108.95 ; 81.75,108.95 81.75,108.05 ; 81.75,108.95 81.04,109.66 ; 81.75,108.95 82.46,109.66 ; 81.75,108.95 80.85,108.95 ; 70.88,34.64 JT31.3 ; JT31.3 71.59,36.26 ; JT31.3 70.88,36.44 ; JT31.3 69.97,35.54 ; JT31.3 71.78,35.54 ; JT31.3 70.16,34.83 ; JT31.3 71.59,34.83 ; JT17.12 69.18,85.12 ; JT17.12 67.75,85.12 ; JT17.12 67.75,86.55 ; JT17.12 68.46,84.93 ; JT17.12 67.56,85.84 ; JT17.12 69.18,86.55 ; JT17.12 68.46,86.74 ; JT17.12 69.36,85.84 ; JT40.3 149.9,37.28 ; JT40.3 150.09,37.99 ; JT40.3 148.48,38.71 ; JT40.3 149.19,37.09 ; JT40.3 149.9,38.71 ; JT40.3 149.19,38.89 ; JT40.3 148.29,37.99 ; JT13.2 189.28,94.12 ; JT13.2 187.66,94.83 ; JT13.2 187.66,93.41 ; JT13.2 187.47,94.12 ; JT13.2 188.37,95.02 ; JT13.2 188.37,93.22 ; JT13.2 189.09,93.41 ; JT14.3 189.28,90.95 ; JT14.3 187.47,90.95 ; JT14.3 188.37,90.04 ; JT14.3 188.37,91.85 ; JT14.3 187.66,90.23 ; JT14.3 189.09,91.66 ; JT14.3 187.66,91.66 ; 101.68,35.54 JT35.4 ; JT35.4 103.29,34.83 ; JT35.4 102.58,34.64 ; JT35.4 101.86,34.83 ; JT35.4 103.48,35.54 ; JT35.4 103.29,36.26 ; JT35.4 102.58,36.44 ; JB6.12 38.06,4.23 ; JB6.12 35.87,4.23 ; JB6.12 36.96,3.14 ; JB6.12 36.96,5.32 ; JB6.12 36.12,3.38 ; JB6.12 36.12,5.08 ; JB6.12 37.81,3.38 ; JB6.12 37.81,5.08 ; JT14.2 188.37,89.31 ; JT14.2 189.28,88.41 ; JT14.2 187.66,87.69 ; JT14.2 188.37,87.5 ; JT14.2 189.09,87.69 ; JT14.2 187.66,89.12 ; JT14.2 187.47,88.41 ; 87.13,109.66 87.85,108.95 ; 87.85,108.95 87.85,109.85 ; 87.85,108.95 88.01,108.95 ; 87.85,108.95 86.94,108.95 ; 87.85,108.95 87.13,108.24 ; 87.85,108.95 88.56,109.66 ; 87.85,108.95 87.85,108.05 ; JB2.12 30.19,139.92 ; JB2.12 29.34,141.86 ; JB2.12 30.19,141.62 ; JB2.12 28.5,141.62 ; JB2.12 30.44,140.77 ; JB2.12 28.5,139.92 ; JB2.12 28.25,140.77 ; JB2.12 29.34,139.68 ; 87.13,34.83 JT33.5 ; JT33.5 87.85,36.44 ; JT33.5 86.94,35.54 ; JT33.5 87.85,34.64 ; JT33.5 88.56,34.83 ; JT33.5 88.75,35.54 ; JT33.5 87.13,36.26 ; 190.2,53.18 JT27.4 ; JT27.4 191.82,53.9 ; JT27.4 190.91,54.8 ; JT27.4 190.91,53 ; JT27.4 191.63,54.61 ; JT27.4 190.01,53.9 ; JT27.4 191.63,53.18 ; 197.57,86.07 JT15.2 ; JT15.2 199.09,86.07 ; JT15.2 197.37,86.83 ; JT15.2 199.09,87.58 ; JT15.2 197.57,87.58 ; JT15.2 198.33,85.86 ; JT15.2 198.33,87.79 ; JT15.2 199.3,86.83 ; 190.2,72.18 JT20.3 ; JT20.3 190.91,72.37 ; JT20.3 191.82,71.47 ; JT20.3 191.63,70.75 ; JT20.3 191.63,72.18 ; JT20.3 190.01,71.47 ; JT20.3 190.91,70.57 ; JT14.5 191.82,88.41 ; JT14.5 190.91,87.5 ; JT14.5 190.2,87.69 ; JT14.5 190.91,89.31 ; JT14.5 191.63,89.12 ; JT14.5 191.63,87.69 ; JT14.5 190.01,88.41 ; JT7.5 93.94,107.31 ; JT7.5 94.66,105.7 ; JT7.5 93.04,106.41 ; JT7.5 94.84,106.41 ; JT7.5 93.23,107.12 ; JT7.5 93.23,105.7 ; JT7.5 93.94,105.51 ; JT38.4 125.57,36.17 ; JT38.4 125.76,35.45 ; JT38.4 124.85,36.35 ; JT38.4 125.57,34.74 ; JT38.4 124.14,34.74 ; JT38.4 124.85,34.55 ; JT38.4 123.95,35.45 ; 145.75,37.99 JT40.2 ; JT40.2 146.65,38.89 ; JT40.2 145.94,37.28 ; JT40.2 147.55,37.99 ; JT40.2 146.65,37.09 ; JT40.2 147.36,38.71 ; JT40.2 145.94,38.71 ; 190.2,81.98 JT16.5 ; JT16.5 191.82,82.69 ; JT16.5 190.91,81.79 ; JT16.5 190.91,83.59 ; JT16.5 190.01,82.69 ; JT16.5 191.63,81.98 ; JT16.5 191.63,83.4 ; 105.42,107.12 JT9.5 ; JT9.5 105.42,105.7 ; JT9.5 107.04,106.41 ; JT9.5 105.23,106.41 ; JT9.5 106.13,107.31 ; JT9.5 106.85,105.7 ; JT9.5 106.13,105.51 ; JT28.4 68.34,51.3 ; JT28.4 67.62,51.12 ; JT28.4 68.34,49.5 ; JT28.4 67.43,50.4 ; JT28.4 69.24,50.4 ; JT28.4 67.62,49.69 ; JT28.4 69.05,49.69 ; 190.91,68.03 JT20.4 ; JT20.4 190.2,68.21 ; JT20.4 190.01,68.93 ; JT20.4 191.82,68.93 ; JT20.4 190.91,69.83 ; JT20.4 191.63,68.21 ; JT20.4 191.63,69.64 ; 67.62,53.66 JT28.5 ; JT28.5 68.34,52.04 ; JT28.5 67.43,52.94 ; JT28.5 69.05,53.66 ; JT28.5 68.34,53.84 ; JT28.5 67.62,52.23 ; JT28.5 69.24,52.94 ; JT25.2 71.78,57.89 ; JT25.2 71.59,57.18 ; JT25.2 70.16,58.61 ; JT25.2 70.88,58.8 ; JT25.2 71.59,58.61 ; JT25.2 70.88,56.99 ; JT25.2 69.97,57.89 ; 87.85,37.18 JT33.2 ; JT33.2 87.85,38.98 ; JT33.2 86.94,38.08 ; JT33.2 87.13,37.37 ; JT33.2 87.13,38.8 ; JT33.2 88.75,38.08 ; JT33.2 88.56,38.8 ; JT41.5 187.74,31.91 ; JT41.5 187.5,32.76 ; JT41.5 186.65,30.82 ; JT41.5 186.65,33 ; JT41.5 185.56,31.91 ; JT41.5 187.5,31.06 ; JT41.5 185.8,32.76 ; JT41.5 185.8,31.06 ; 188.37,60.51 JT23.5 ; JT23.5 187.47,61.41 ; JT23.5 187.66,62.13 ; JT23.5 189.28,61.41 ; JT23.5 189.09,60.7 ; JT23.5 188.37,62.31 ; JT23.5 187.66,60.7 ; 198.78,10.79 UT36.2 ; UT36.2 198.78,12.29 ; UT36.2 198.57,11.54 ; UT36.2 199.53,10.59 ; UT36.2 199.53,12.49 ; UT36.2 200.28,12.29 ; UT36.2 200.28,10.79 ; UT36.2 200.48,11.54 ; 67.62,63.56 JT24.5 ; JT24.5 68.34,63.75 ; JT24.5 67.62,62.13 ; JT24.5 69.05,63.56 ; JT24.5 67.43,62.85 ; JT24.5 69.24,62.85 ; JT24.5 68.34,61.95 ; JT12.2 151.6,105.7 ; JT12.2 149.98,106.41 ; JT12.2 151.79,106.41 ; JT12.2 150.17,105.7 ; JT12.2 150.89,105.51 ; JT12.2 150.17,107.12 ; JT12.2 150.89,107.31 ; 95.77,109.66 96.48,108.95 ; 96.48,108.95 97.2,109.66 ; 96.48,108.95 95.58,108.95 ; 96.48,108.95 97.38,108.95 ; 96.48,108.95 96.48,108.05 ; 96.48,108.95 96.48,109.85 ; 96.48,108.95 97.2,108.24 ; JT20.5 189.09,68.21 ; JT20.5 188.37,68.03 ; JT20.5 187.66,69.64 ; JT20.5 188.37,69.83 ; JT20.5 187.47,68.93 ; JT20.5 189.28,68.93 ; JT20.5 187.66,68.21 ; 41.2,5.08 JB6.16 ; JB6.16 43.14,4.23 ; JB6.16 42.04,5.32 ; JB6.16 40.95,4.23 ; JB6.16 41.2,3.38 ; JB6.16 42.89,5.08 ; JB6.16 42.04,3.14 ; JB6.16 42.89,3.38 ; JT28.2 71.59,52.23 ; JT28.2 70.88,52.04 ; JT28.2 70.88,53.84 ; JT28.2 69.97,52.94 ; JT28.2 71.78,52.94 ; JT28.2 70.16,53.66 ; JT28.2 71.59,53.66 ; 90.39,108.05 90.39,108.95 ; 90.39,108.95 91.03,108.95 ; 90.39,108.95 89.48,108.95 ; 90.39,108.95 91.1,108.24 ; 90.39,108.95 89.67,109.66 ; 90.39,108.95 90.39,109.85 ; 90.39,108.95 91.1,109.66 ; JT23.3 191.63,64.67 ; JT23.3 190.2,64.67 ; JT23.3 190.91,64.85 ; JT23.3 191.63,63.24 ; JT23.3 190.91,63.05 ; JT23.3 190.01,63.95 ; JT23.3 191.82,63.95 ; JT35.5 100.75,34.83 ; JT35.5 99.14,35.54 ; JT35.5 99.32,36.26 ; JT35.5 100.04,36.44 ; JT35.5 99.32,34.83 ; JT35.5 100.04,34.64 ; JT35.5 100.94,35.54 ; 100.89,3.38 JB8.16 ; JB8.16 102.83,4.23 ; JB8.16 100.89,5.08 ; JB8.16 102.58,3.38 ; JB8.16 102.58,5.08 ; JB8.16 100.64,4.23 ; JB8.16 101.73,3.14 ; JB8.16 101.73,5.32 ; JT21.3 71.59,68.51 ; JT21.3 70.88,66.9 ; JT21.3 70.88,68.7 ; JT21.3 71.78,67.8 ; JT21.3 71.59,67.09 ; JT21.3 69.97,67.8 ; JT21.3 70.16,68.51 ; 171.91,116.22 JT2.8 ; JT2.8 172.76,116.47 ; JT2.8 172.76,114.28 ; JT2.8 173.85,115.38 ; JT2.8 171.91,114.53 ; JT2.8 173.6,116.22 ; JT2.8 171.66,115.38 ; JT2.8 173.6,114.53 ; JT29.2 70.88,48.89 ; JT29.2 71.59,48.7 ; JT29.2 70.16,48.7 ; JT29.2 70.88,47.09 ; JT29.2 71.78,47.99 ; JT29.2 69.97,47.99 ; JT29.2 71.59,47.28 ; 84.29,108.95 85,109.66 ; 84.29,108.95 83.39,108.95 ; 84.29,108.95 85.19,108.95 ; 84.29,108.95 83.58,109.66 ; 84.29,108.95 85,108.24 ; 84.29,108.95 84.29,108.05 ; 84.29,108.95 84.29,109.85 ; JT13.4 191.82,96.66 ; JT13.4 191.63,97.37 ; JT13.4 190.2,97.37 ; JT13.4 190.01,96.66 ; JT13.4 191.63,95.95 ; JT13.4 190.91,95.76 ; JT13.4 190.91,97.56 ; 150.17,108.24 150.89,108.95 ; 150.89,108.95 150.17,109.66 ; 150.89,108.95 150.89,109.85 ; 150.89,108.95 151.6,109.66 ; 150.89,108.95 150.89,108.05 ; 150.89,108.95 149.98,108.95 ; 150.89,108.95 151.79,108.95 ; 152.52,106.41 JT12.5 ; JT12.5 152.71,105.7 ; JT12.5 153.43,105.51 ; JT12.5 154.14,105.7 ; JT12.5 154.14,107.12 ; JT12.5 154.33,106.41 ; JT12.5 153.43,107.31 ; 114.06,38.8 JT37.3 ; JT37.3 115.48,37.37 ; JT37.3 114.77,37.18 ; JT37.3 114.77,38.98 ; JT37.3 115.48,38.8 ; JT37.3 113.87,38.08 ; JT37.3 115.67,38.08 ; JT4.3 138.69,109.98 ; JT4.3 137.79,109.08 ; JT4.3 139.41,109.79 ; JT4.3 139.6,109.08 ; JT4.3 137.98,108.36 ; JT4.3 137.98,109.79 ; JT4.3 138.69,108.17 ; JB1.S1 190.85,143.97 ; JB1.S1 191.97,143.62 ; JB1.S1 190.85,141.02 ; JB1.S1 189.38,142.5 ; JB1.S1 191.97,141.38 ; JB1.S1 189.73,143.62 ; JB1.S1 192.32,142.5 ; 190.91,93.22 JT13.5 ; JT13.5 190.01,94.12 ; JT13.5 191.63,94.83 ; JT13.5 190.91,95.02 ; JT13.5 191.63,93.41 ; JT13.5 190.2,93.41 ; JT13.5 191.82,94.12 ; 89.67,105.7 JT6.4 ; JT6.4 91.03,106.41 ; JT6.4 90.39,107.31 ; JT6.4 91.1,107.12 ; JT6.4 90.39,105.51 ; JT6.4 89.48,106.41 ; JT6.4 91.1,105.7 ; 152.52,108.95 153.43,108.95 ; 153.43,108.95 152.71,109.66 ; 153.43,108.95 154.14,109.66 ; 153.43,108.95 154.14,108.24 ; 153.43,108.95 153.43,108.05 ; 153.43,108.95 153.43,109.85 ; 153.43,108.95 154.33,108.95 ; JT24.3 71.59,61.02 ; JT24.3 70.88,61.21 ; JT24.3 70.16,59.59 ; JT24.3 69.97,60.31 ; JT24.3 71.59,59.59 ; JT24.3 70.88,59.41 ; JT24.3 71.78,60.31 ; 108.67,108.95 108.67,109.85 ; 108.67,108.95 109.58,108.95 ; 108.67,108.95 107.96,109.66 ; 108.67,108.95 109.39,108.24 ; 108.67,108.95 109.39,109.66 ; 108.67,108.95 107.77,108.95 ; 108.67,108.95 108.67,108.05 ; 180.69,13.99 JB5.1 ; JB5.1 182.21,13.99 ; JB5.1 180.49,14.74 ; JB5.1 182.21,15.5 ; JB5.1 182.42,14.74 ; JB5.1 181.45,15.71 ; JB5.1 181.45,13.78 ; JB5.1 180.69,15.5 ; 138.13,53.58 JT26.G1 ; JT26.G1 138.98,52.73 ; JT26.G1 138.98,54.44 ; JT26.G1 139.84,53.58 ; JT26.G1 138.3,54.26 ; JT26.G1 138.3,52.9 ; JT26.G1 139.66,54.26 ; JT26.G1 139.66,52.9 ; 187.66,63.24 JT23.2 ; JT23.2 188.37,64.85 ; JT23.2 189.28,63.95 ; JT23.2 189.09,64.67 ; JT23.2 187.66,64.67 ; JT23.2 187.47,63.95 ; JT23.2 188.37,63.05 ; JT21.2 69.24,67.8 ; JT21.2 67.62,68.51 ; JT21.2 67.43,67.8 ; JT21.2 67.62,67.09 ; JT21.2 69.05,68.51 ; JT21.2 68.34,68.7 ; JT21.2 68.34,66.9 ; 190.2,75.73 JT19.4 ; JT19.4 190.91,75.54 ; JT19.4 190.91,77.35 ; JT19.4 191.82,76.44 ; JT19.4 190.01,76.44 ; JT19.4 191.63,75.73 ; JT19.4 191.63,77.16 ; JT32.3 85.19,38.08 ; JT32.3 84.29,37.18 ; JT32.3 85,37.37 ; JT32.3 83.39,38.08 ; JT32.3 84.29,38.98 ; JT32.3 85,38.8 ; JT32.3 83.58,38.8 ; 187.66,79.7 JT19.2 ; JT19.2 187.66,78.27 ; JT19.2 187.47,78.98 ; JT19.2 189.28,78.98 ; JT19.2 188.37,78.08 ; JT19.2 189.09,79.7 ; JT19.2 188.37,79.89 ; 187.66,81.98 JT16.2 ; JT16.2 189.28,82.69 ; JT16.2 188.37,83.59 ; JT16.2 189.09,81.98 ; JT16.2 188.37,81.79 ; JT16.2 187.47,82.69 ; JT16.2 187.66,83.4 ; 95.81,5.08 JB8.12 ; JB8.12 97.75,4.23 ; JB8.12 95.81,3.38 ; JB8.12 96.65,3.14 ; JB8.12 95.56,4.23 ; JB8.12 96.65,5.32 ; JB8.12 97.5,5.08 ; JB8.12 97.5,3.38 ; JT2.2 165.98,116.22 ; JT2.2 165.14,116.47 ; JT2.2 164.29,114.53 ; JT2.2 165.98,114.53 ; JT2.2 165.14,114.28 ; JT2.2 164.29,116.22 ; JT2.2 164.04,115.38 ; JT2.2 166.23,115.38 ; 67.62,47.28 JT29.5 ; JT29.5 67.43,47.99 ; JT29.5 69.05,48.7 ; JT29.5 69.24,47.99 ; JT29.5 67.62,48.7 ; JT29.5 68.34,48.89 ; JT29.5 68.34,47.09 ; JT31.4 68.34,36.44 ; JT31.4 67.62,34.83 ; JT31.4 67.62,36.26 ; JT31.4 69.05,34.83 ; JT31.4 67.43,35.54 ; JT31.4 68.34,34.64 ; JT31.4 69.24,35.54 ; 105.23,38.08 JT36.2 ; JT36.2 105.42,38.8 ; JT36.2 106.13,37.18 ; JT36.2 107.04,38.08 ; JT36.2 106.85,38.8 ; JT36.2 106.13,38.98 ; JT36.2 105.42,37.37 ; 95.58,106.41 JT7.4 ; JT7.4 97.2,105.7 ; JT7.4 97.38,106.41 ; JT7.4 96.48,105.51 ; JT7.4 95.77,105.7 ; JT7.4 96.48,107.31 ; JT7.4 97.2,107.12 ; 126.58,105.51 JT11.2 ; JT11.2 125.68,106.41 ; JT11.2 127.48,106.41 ; JT11.2 125.86,105.7 ; JT11.2 126.58,107.31 ; JT11.2 127.29,105.7 ; JT11.2 125.86,107.12 ; JB4.16 83.95,141.86 ; JB4.16 83.95,139.68 ; JB4.16 84.8,141.62 ; JB4.16 84.8,139.92 ; JB4.16 82.86,140.77 ; JB4.16 83.11,139.92 ; JB4.16 85.05,140.77 ; JB4.16 83.11,141.62 ; 188.37,55.54 JT27.2 ; JT27.2 187.47,56.44 ; JT27.2 188.37,57.34 ; JT27.2 189.09,57.15 ; JT27.2 187.66,55.72 ; JT27.2 189.28,56.44 ; JT27.2 187.66,57.15 ; JT32.5 82.46,34.83 ; JT32.5 80.85,35.54 ; JT32.5 81.75,34.64 ; JT32.5 81.04,34.83 ; JT32.5 82.65,35.54 ; JT32.5 81.75,36.44 ; JT32.5 81.04,36.26 ; JT34.3 97.2,37.37 ; JT34.3 96.48,38.98 ; JT34.3 95.58,38.08 ; JT34.3 97.2,38.8 ; JT34.3 96.48,37.18 ; JT34.3 95.77,38.8 ; JT34.3 97.38,38.08 ; JB4.14 87.34,139.92 ; JB4.14 85.65,141.62 ; JB4.14 85.4,140.77 ; JB4.14 86.49,139.68 ; JB4.14 87.34,141.62 ; JB4.14 85.65,139.92 ; JB4.14 86.49,141.86 ; JB4.14 87.59,140.77 ; JB2.14 27.65,141.62 ; JB2.14 26.8,139.68 ; JB2.14 25.96,139.92 ; JB2.14 25.71,140.77 ; JB2.14 25.96,141.62 ; JB2.14 26.8,141.86 ; JB2.14 27.65,139.92 ; JB2.14 27.9,140.77 ; JT8.5 100.04,107.31 ; JT8.5 100.04,105.51 ; JT8.5 99.32,105.7 ; JT8.5 99.32,107.12 ; JT8.5 100.75,105.7 ; JT8.5 100.94,106.41 ; JT8.5 99.14,106.41 ; JB4.2 102.83,140.77 ; JB4.2 102.58,141.62 ; JB4.2 101.73,141.86 ; JB4.2 100.64,140.77 ; JB4.2 101.73,139.68 ; JB4.2 100.89,139.92 ; JB4.2 100.89,141.62 ; JB4.2 102.58,139.92 ; 93.23,37.37 JT34.2 ; JT34.2 94.84,38.08 ; JT34.2 93.94,38.98 ; JT34.2 93.94,37.18 ; JT34.2 94.66,38.8 ; JT34.2 93.04,38.08 ; JT34.2 93.23,38.8 ; 190.91,84.33 JT16.4 ; JT16.4 190.01,85.23 ; JT16.4 190.91,86.13 ; JT16.4 191.63,85.94 ; JT16.4 190.2,85.94 ; JT16.4 191.82,85.23 ; JT16.4 191.63,84.52 ; JB5.S2 190.85,3.98 ; JB5.S2 189.38,2.5 ; JB5.S2 191.97,1.38 ; JB5.S2 190.85,1.03 ; JB5.S2 192.32,2.5 ; JB5.S2 191.97,3.62 ; JB5.S2 189.73,1.38 ; 23.17,140.77 JB2.16 ; JB2.16 24.26,141.86 ; JB2.16 25.36,140.77 ; JB2.16 24.26,139.68 ; JB2.16 25.11,139.92 ; JB2.16 23.42,141.62 ; JB2.16 25.11,141.62 ; JB2.16 23.42,139.92 ; JT32.4 84.29,36.44 ; JT32.4 85.19,35.54 ; JT32.4 84.29,34.64 ; JT32.4 83.58,34.83 ; JT32.4 83.39,35.54 ; JT32.4 85,34.83 ; JT32.4 85,36.26 ; JT10.5 112.23,107.31 ; JT10.5 111.52,105.7 ; JT10.5 113.13,106.41 ; JT10.5 111.52,107.12 ; JT10.5 112.94,105.7 ; JT10.5 112.23,105.51 ; JT10.5 111.33,106.41 ; JT36.3 109.39,38.8 ; JT36.3 107.77,38.08 ; JT36.3 108.67,38.98 ; JT36.3 109.39,37.37 ; JT36.3 109.58,38.08 ; JT36.3 107.96,38.8 ; JT36.3 108.67,37.18 ; JT38.5 123.03,34.74 ; JT38.5 122.31,34.55 ; JT38.5 121.6,34.74 ; JT38.5 121.41,35.45 ; JT38.5 121.6,36.17 ; JT38.5 123.22,35.45 ; JT38.5 122.31,36.35 ; JT39.2 135.38,37.99 ; JT39.2 133.77,38.71 ; JT39.2 133.77,37.28 ; JT39.2 135.2,38.71 ; JT39.2 134.48,37.09 ; JT39.2 134.48,38.89 ; JT39.2 133.58,37.99 ; 68.26,4.23 JB7.14 ; JB7.14 68.5,5.08 ; JB7.14 70.2,5.08 ; JB7.14 70.44,4.23 ; JB7.14 69.35,3.14 ; JB7.14 70.2,3.38 ; JB7.14 68.5,3.38 ; JB7.14 69.35,5.32 ; JT23.4 191.63,60.7 ; JT23.4 190.91,62.31 ; JT23.4 191.63,62.13 ; JT23.4 190.2,60.7 ; JT23.4 190.01,61.41 ; JT23.4 191.82,61.41 ; JT23.4 190.91,60.51 ; 187.47,71.47 JT20.2 ; JT20.2 188.37,72.37 ; JT20.2 187.66,70.75 ; JT20.2 189.09,72.18 ; JT20.2 188.37,70.57 ; JT20.2 187.66,72.18 ; JT20.2 189.28,71.47 ; 69.97,45.45 JT29.3 ; JT29.3 71.78,45.45 ; JT29.3 71.59,44.74 ; JT29.3 70.88,44.55 ; JT29.3 70.16,44.74 ; JT29.3 71.59,46.16 ; JT29.3 70.88,46.35 ; 89.67,38.8 JT33.3 ; JT33.3 91.1,37.37 ; JT33.3 91.1,38.8 ; JT33.3 90.39,38.98 ; JT33.3 91.29,38.08 ; JT33.3 90.39,37.18 ; JT33.3 89.48,38.08 ; 89.67,34.83 JT33.4 ; JT33.4 91.29,35.54 ; JT33.4 90.39,36.44 ; JT33.4 89.48,35.54 ; JT33.4 91.1,36.26 ; JT33.4 91.1,34.83 ; JT33.4 90.39,34.64 ; 83.95,3.14 JB8.2 ; JB8.2 85.05,4.23 ; JB8.2 83.11,3.38 ; JB8.2 83.95,5.32 ; JB8.2 84.8,3.38 ; JB8.2 82.86,4.23 ; JB8.2 84.8,5.08 ; JB8.2 83.11,5.08 ; 67.62,38.8 JT31.5 ; JT31.5 69.24,38.08 ; JT31.5 68.34,37.18 ; JT31.5 67.43,38.08 ; JT31.5 68.34,38.98 ; JT31.5 67.62,37.37 ; JT31.5 69.05,38.8 ; JT40.5 147.36,34.74 ; JT40.5 145.94,36.17 ; JT40.5 146.65,34.55 ; JT40.5 145.75,35.45 ; JT40.5 145.94,34.74 ; JT40.5 147.55,35.45 ; JT40.5 146.65,36.35 ; 128.4,109.66 129.12,108.95 ; 129.12,108.95 129.12,108.05 ; 129.12,108.95 129.83,108.24 ; 129.12,108.95 129.83,109.66 ; 129.12,108.95 128.22,108.95 ; 129.12,108.95 129.12,109.85 ; 129.12,108.95 130.02,108.95 ; 67.62,65.97 JT21.5 ; JT21.5 69.24,65.26 ; JT21.5 67.62,64.55 ; JT21.5 69.05,64.55 ; JT21.5 67.43,65.26 ; JT21.5 68.34,66.16 ; JT21.5 68.34,64.36 ; JT30.3 71.59,39.78 ; JT30.3 71.59,41.21 ; JT30.3 70.88,39.59 ; JT30.3 71.78,40.5 ; JT30.3 70.88,41.4 ; JT30.3 69.97,40.5 ; JT30.3 70.16,39.78 ; 187.66,84.52 JT16.3 ; JT16.3 189.28,85.23 ; JT16.3 187.47,85.23 ; JT16.3 187.66,85.94 ; JT16.3 189.09,85.94 ; JT16.3 188.37,84.33 ; JT16.3 188.37,86.13 ; JB1.S2 190.85,128.38 ; JB1.S2 190.85,125.43 ; JB1.S2 192.32,126.9 ; JB1.S2 191.97,125.78 ; JB1.S2 191.97,128.02 ; JB1.S2 189.73,125.78 ; JB1.S2 189.38,126.9 ; JT37.5 112.23,36.44 ; JT37.5 111.52,34.83 ; JT37.5 112.94,34.83 ; JT37.5 113.13,35.54 ; JT37.5 112.23,34.64 ; JT37.5 111.33,35.54 ; JT37.5 111.52,36.26 ; 101.68,106.41 JT8.4 ; JT8.4 101.86,105.7 ; JT8.4 103.29,107.12 ; JT8.4 103.48,106.41 ; JT8.4 102.58,105.51 ; JT8.4 102.58,107.31 ; JT8.4 103.29,105.7 ; JT10.4 115.67,106.41 ; JT10.4 115.48,107.12 ; JT10.4 113.87,106.41 ; JT10.4 115.48,105.7 ; JT10.4 114.77,107.31 ; JT10.4 114.77,105.51 ; JT10.4 114.06,105.7 ; JT26.G3 156.45,52.9 ; JT26.G3 155.77,54.44 ; JT26.G3 155.77,52.73 ; JT26.G3 156.62,53.58 ; JT26.G3 156.45,54.26 ; JT26.G3 155.09,54.26 ; JT26.G3 155.09,52.9 ; JT26.G3 154.92,53.58 ; 107.77,35.54 JT36.4 ; JT36.4 108.67,34.64 ; JT36.4 109.39,36.26 ; JT36.4 109.39,34.83 ; JT36.4 109.58,35.54 ; JT36.4 108.67,36.44 ; JT36.4 107.96,34.83 ; 67.62,42.32 JT30.5 ; JT30.5 67.62,43.75 ; JT30.5 69.24,43.04 ; JT30.5 68.34,42.13 ; JT30.5 67.43,43.04 ; JT30.5 68.34,43.94 ; JT30.5 69.05,43.75 ; JT30.2 71.59,43.75 ; JT30.2 70.88,43.94 ; JT30.2 71.78,43.04 ; JT30.2 71.59,42.32 ; JT30.2 69.97,43.04 ; JT30.2 70.16,43.75 ; JT30.2 70.88,42.13 ; 54.11,139.68 JB3.16 ; JB3.16 53.26,141.62 ; JB3.16 55.2,140.77 ; JB3.16 53.02,140.77 ; JB3.16 54.11,141.86 ; JB3.16 54.96,139.92 ; JB3.16 53.26,139.92 ; JB3.16 54.96,141.62 ; JT11.5 129.83,105.7 ; JT11.5 129.83,107.12 ; JT11.5 128.22,106.41 ; JT11.5 128.4,105.7 ; JT11.5 129.12,105.51 ; JT11.5 129.12,107.31 ; JT11.5 130.02,106.41 ; 70.16,54.64 JT25.3 ; JT25.3 71.59,54.64 ; JT25.3 70.88,54.45 ; JT25.3 70.88,56.26 ; JT25.3 71.78,55.36 ; JT25.3 69.97,55.36 ; JT25.3 71.59,56.07 ; JT24.2 71.78,62.85 ; JT24.2 70.88,61.95 ; JT24.2 71.59,63.56 ; JT24.2 69.97,62.85 ; JT24.2 70.88,63.75 ; JT24.2 70.16,63.56 ; JT24.2 71.59,62.13 ; 105.23,108.95 106.13,108.95 ; 106.13,108.95 107.04,108.95 ; 106.13,108.95 106.13,108.05 ; 106.13,108.95 106.85,109.66 ; 106.13,108.95 105.42,108.24 ; 106.13,108.95 106.13,109.85 ; 106.13,108.95 105.42,109.66 ; 83.6,54.26 JT26.G2 ; JT26.G2 83.43,53.58 ; JT26.G2 84.96,52.9 ; JT26.G2 84.28,52.73 ; JT26.G2 85.14,53.58 ; JT26.G2 84.96,54.26 ; JT26.G2 84.28,54.44 ; JT26.G2 83.6,52.9 ; 190.01,90.95 JT14.4 ; JT14.4 191.82,90.95 ; JT14.4 190.91,90.04 ; JT14.4 190.91,91.85 ; JT14.4 190.2,91.66 ; JT14.4 191.63,90.23 ; JT14.4 191.63,91.66 ; 187.66,77.16 JT19.5 ; JT19.5 188.37,77.35 ; JT19.5 187.47,76.44 ; JT19.5 189.09,75.73 ; JT19.5 187.66,75.73 ; JT19.5 189.28,76.44 ; JT19.5 188.37,75.54 ; 71.04,3.38 JB7.16 ; JB7.16 72.74,3.38 ; JB7.16 72.98,4.23 ; JB7.16 70.8,4.23 ; JB7.16 71.89,3.14 ; JB7.16 72.74,5.08 ; JB7.16 71.89,5.32 ; JB7.16 71.04,5.08 ; JT39.4 137.74,36.17 ; JT39.4 136.12,35.45 ; JT39.4 137.02,36.35 ; JT39.4 137.02,34.55 ; JT39.4 137.92,35.45 ; JT39.4 137.74,34.74 ; JT39.4 136.31,34.74 ; JT41.10 184.96,37.84 ; JT41.10 184.11,35.9 ; JT41.10 183.26,36.14 ; JT41.10 184.96,36.14 ; JT41.10 185.2,36.99 ; JT41.10 183.26,37.84 ; JT41.10 183.02,36.99 ; JT41.10 184.11,38.08 ; 58.34,139.92 JB3.12 ; JB3.12 60.28,140.77 ; JB3.12 60.04,141.62 ; JB3.12 58.34,141.62 ; JB3.12 58.1,140.77 ; JB3.12 60.04,139.92 ; JB3.12 59.19,141.86 ; JB3.12 59.19,139.68 ; 122.31,37.09 JT38.2 ; JT38.2 121.6,38.71 ; JT38.2 123.22,37.99 ; JT38.2 122.31,38.89 ; JT38.2 123.03,38.71 ; JT38.2 121.41,37.99 ; JT38.2 121.6,37.28 ; 114.77,34.64 JT37.4 ; JT37.4 114.06,34.83 ; JT37.4 115.48,34.83 ; JT37.4 115.67,35.54 ; JT37.4 115.48,36.26 ; JT37.4 114.77,36.44 ; JT37.4 113.87,35.54 ; 125.68,108.95 126.58,108.95 ; 126.58,108.95 126.58,108.05 ; 126.58,108.95 125.86,109.66 ; 126.58,108.95 127.29,109.66 ; 126.58,108.95 126.58,109.85 ; 126.58,108.95 125.86,108.24 ; 126.58,108.95 127.48,108.95 ; 105.42,34.83 JT36.5 ; JT36.5 106.85,34.83 ; JT36.5 106.13,36.44 ; JT36.5 106.13,34.64 ; JT36.5 105.23,35.54 ; JT36.5 107.04,35.54 ; JT36.5 105.42,36.26 ; 187.66,95.95 JT13.3 ; JT13.3 189.09,97.37 ; JT13.3 189.28,96.66 ; JT13.3 187.47,96.66 ; JT13.3 188.37,97.56 ; JT13.3 188.37,95.76 ; JT13.3 187.66,97.37 ; 68.34,56.99 JT25.5 ; JT25.5 67.62,58.61 ; JT25.5 67.43,57.89 ; JT25.5 68.34,58.8 ; JT25.5 69.05,58.61 ; JT25.5 67.62,57.18 ; JT25.5 69.24,57.89 ; 180.49,139.14 JB1.1 ; JB1.1 181.45,140.11 ; JB1.1 182.21,139.9 ; JB1.1 180.69,138.39 ; JB1.1 181.45,138.18 ; JB1.1 182.21,138.39 ; JB1.1 180.69,139.9 ; JB1.1 182.42,139.14 ; 67.62,44.74 JT29.4 ; JT29.4 69.05,44.74 ; JT29.4 69.24,45.45 ; JT29.4 68.34,44.55 ; JT29.4 67.43,45.45 ; JT29.4 67.62,46.16 ; JT29.4 68.34,46.35
  BOTTOM w0.254: UB4.1 95.71,91.26 96.04,91.59 v1(96.04,92.15) 95.08,92.15 CB13.2 ; UB4.4 96.42,89.35 v1(96.54,89.23) ; CB14.2 105.26,92.15 v1(106.21,92.15) 106.21,91.59 105.88,91.26 UB5.1 ; UB11.1 105.37,77 105.7,77.33 v1(105.7,77.89) 104.75,77.89 CB29.2 ; UB3.4 86.24,89.35 v1(86.37,89.23) ; UB11.4 106.08,75.09 v1(106.21,74.96) ; UB9.1 85.53,77 85.86,77.33 v1(85.86,77.89) 84.91,77.89 CB27.2 ; CB12.2 84.91,92.15 v1(85.86,92.15) 85.86,91.59 85.53,91.26 UB3.1 ; UB10.1 95.45,77 95.78,77.33 v1(95.78,77.89) 94.83,77.89 CB28.2 ; v1(86.37,74.96) 86.24,75.09 UB9.4 ; UB5.4 106.59,89.35 v1(106.72,89.23) ; UB10.4 96.16,75.09 v1(96.29,74.96)
  BOTTOM w0.381: v1(86.22,64.95) CB48.2 CB49.2 ; CB3.1 RB11.2 153.81,118.01 153.47,118.35 v1(152.8,118.35) ; v1(99.2,65.03) 99.24,64.99 CB52.2 CB53.2 ; RB116.2 CB79.2 210.1,38.3 v1(210.58,38.79) ; RB119.2 CB84.2 199.91,46.72 v1(198.99,46.72) ; UB20.2 158.11,41.92 157.73,41.54 156.72,41.54 156.36,41.9 CB68.2 v1(155.54,42.94) ; RB4.1 76.45,123.34 v1(77.12,122.66) ; CB72.2 174.29,29.4 173.24,30.46 ; CB72.2 CB73.2 175.99,30.05 177.05,31.11 UB22.22 ; CB72.2 v1(174.29,26.95) ; RB5.2 98.53,117.97 99.82,119.26 v1(100.52,119.26) ; v1(97.83,31.99) 97.94,31.87 97.94,31.63 98.65,30.92 RB90.1 ; CB43.2 v1(161.22,69.23) ; RB109.2 98.61,21.57 99.9,22.86 v1(100.6,22.86) ; CB11.2 75.47,94.39 CB10.1 RB28.1 v1(72.33,93.38) ; v1(76.05,25.58) 75.38,26.26 RB96.1 ; v1(97.8,129.15) 97.92,129.03 97.92,128.79 98.63,128.08 RB1.1 ; 173.24,30.46 173.75,30.97 173.75,35.8 173.24,36.31 172.19,36.31 UB22.12 ; 173.24,30.46 UB22.2 ; v1(128.46,118.35) 129.14,118.35 129.48,118.01 RB7.2 CB1.1 ; 178.09,36.31 v1(179.9,36.31) ; 178.09,36.31 UB22.13 ; 178.09,36.31 UB22.15 ; CB54.2 160.71,62.49 159.03,62.49 158.65,62.87 UB17.2 v1(158.65,64.64) ; CB76.1 RB102.2 146.32,25.16 146.66,24.82 v1(147.33,24.82) ; RB115.2 CB83.2 200.07,37.8 v1(198.99,37.8) ; v1(178.84,68.12) CB45.2 178.36,66.58 UB19.19 ; CB74.1 RB98.2 121.98,25.16 122.32,24.82 v1(123,24.82) ; CB2.1 RB9.2 141.64,118.01 141.31,118.35 v1(140.63,118.35) ; v1(75.8,112.78) 76.33,113.3 RB14.2 ; v1(169.95,68.25) CB44.2 169.65,66.76 UB18.19 ; RB120.2 CB81.2 209.87,47.26 210.15,47.54 v1(210.77,47.54) ; CB75.1 RB100.2 134.15,25.16 134.49,24.82 v1(135.17,24.82) ; RB112.2 75.56,16.91 v1(75.04,16.39) ; UB15.2 v1(158.65,69.62) ; UB19.1 178.95,59.22 178.95,60.06 178.74,60.28 176.68,60.28 176.46,60.06 176.46,59.22 UB19.5 UB19.6 UB19.7 UB19.8 UB19.9 UB19.10 v1(171.61,59.16) UB18.1 UB18.2 UB18.3 168.94,59.22 168.94,60.06 168.72,60.28 164.72,60.28 164.5,60.06 164.5,59.22 UB18.10 ; v1(95.95,65.01) 95.95,63.93 CB51.2 ; CB50.2 v1(92.73,65.1)
  BOTTOM w0.508: CB39.2 v1(98.53,70.73) ; v1(79.83,71.87) CB33.1 81.23,71.45 UB12.2 ; v1(75.8,97.59) CB9.1 74.4,98.01 UB2.2 ; CB4.2 146.12,111.17 146.87,110.42 146.87,109.95 146.92,109.89 UB1.2 146.92,105.94 CB6.2 144.92,105.14 v1(144.51,105.55) 144.25,105.81 CB5.2 ; CB71.2 141.45,32.62 140.65,33.42 UB21.2 140.65,37.85 CB69.2 142.65,38.65 v1(143.06,38.24) 143.33,37.97 CB70.2 ; v1(89.75,71.87) CB34.1 91.15,71.45 UB13.2 ; CB58.2 CB59.2 CB60.2 CB61.2 ; CB58.2 CB57.2 CB56.2 CB55.2 ; CB58.2 v1(92.24,54.05) ; CB47.2 214.75,67.33 214,66.59 213.53,66.59 213.47,66.53 UB16.2 209.52,66.53 CB46.2 208.72,68.53 v1(209.13,68.94) 209.39,69.21 CB36.2 ; CB38.2 v1(88.61,70.73) ; UB14.2 101.07,71.45 CB35.1 v1(99.67,71.87) ; CB8.2 v1(76.94,98.73) ; CB21.2 v1(78.69,84.99) ; UB8.2 101.58,85.71 CB20.1 v1(100.18,86.13) ; v1(90.01,86.13) CB19.1 91.4,85.71 UB7.2 ; CB22.2 v1(88.86,84.99) ; CB67.2 CB66.2 CB65.2 CB64.2 CB63.2 CB62.2 v1(86.98,39.33) ; CB23.2 v1(99.04,84.99) ; UB6.2 81.23,85.71 CB18.1 v1(79.83,86.13) ; CB37.2 v1(78.69,70.73)
  vias: v1(210.58,37.52) v1(210.58,36.25) v1(210.77,46.27) v1(210.77,45) v1(212.05,29.95) v1(212.05,28.69) v1(212.05,27.41) v1(212.05,26.15) v1(212.05,24.88) v1(212.05,23.6) v1(212.05,22.34) v1(213.01,38.85) v1(213.01,37.58) v1(213.01,36.31) v1(213.2,47.59) v1(213.2,46.32) v1(213.2,45.05) v1(213.32,29.95) v1(213.32,28.69) v1(213.32,27.41) v1(213.32,26.15) v1(213.32,24.88) v1(213.32,23.6) v1(213.32,22.34) v1(213.32,21.06) v1(214.59,29.95) v1(214.59,28.69) v1(214.59,27.41) v1(214.59,26.15) v1(214.59,24.88) v1(214.59,23.6) v1(214.59,22.34) v1(214.59,21.06) v1(214.59,19.8) v1(215.86,29.95) v1(215.86,28.69) v1(215.86,27.41) v1(215.86,26.15) v1(215.86,24.88) v1(215.86,23.6) v1(215.86,22.34) v1(215.86,21.06) v1(215.86,19.8) v1(217.13,21.06) v1(217.13,19.8) v1(218.4,21.06) v1(218.4,19.8) v1(219.67,21.06) v1(219.67,19.8) v1(220.94,21.06) v1(220.94,19.8) v1(222.21,29.95) v1(222.21,28.69) v1(222.21,27.41) v1(222.21,26.15) v1(222.21,24.88) v1(227.1,42.4) v1(227.1,41.64) v1(227.86,42.4) v1(227.86,41.64) v1(232.03,41.81) v1(232.03,41.05) v1(232.03,40.28) v1(232.03,39.52) v1(232.03,38.76) v1(232.8,41.81) v1(232.8,41.05) v1(232.8,40.28) v1(232.8,39.52) v1(232.8,38.76) v1(233.56,41.81) v1(233.56,41.05) v1(233.56,40.28) v1(233.56,39.52) v1(233.56,38.76) v1(234.32,41.81) v1(234.32,41.05) v1(234.32,40.28) v1(234.32,39.52) v1(234.32,38.76) v1(241.25,41.79) v1(241.25,41.03) v1(242.01,41.79) v1(242.01,41.03) v2(71.69,107.65) v2(167.22,16.44) v3(238,132.5) v3(238,12.5)
